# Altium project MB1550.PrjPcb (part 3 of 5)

## Sheet MCU_IO.SchDoc: MCU IOs
size A3; Date: Not used; ApprovedBy: Not used; CheckedBy: Not used; Author: Not used; CompanyName: STMicroelectronics; DrawnBy: Not used; Engineer: Not used; Organization: Not used; Address1: Not used; Address2: Not used; Address3: Not used; Address4: Not used; DocumentNumber: 3; Revision: Not used; SheetNumber: 3; SheetTotal: 24
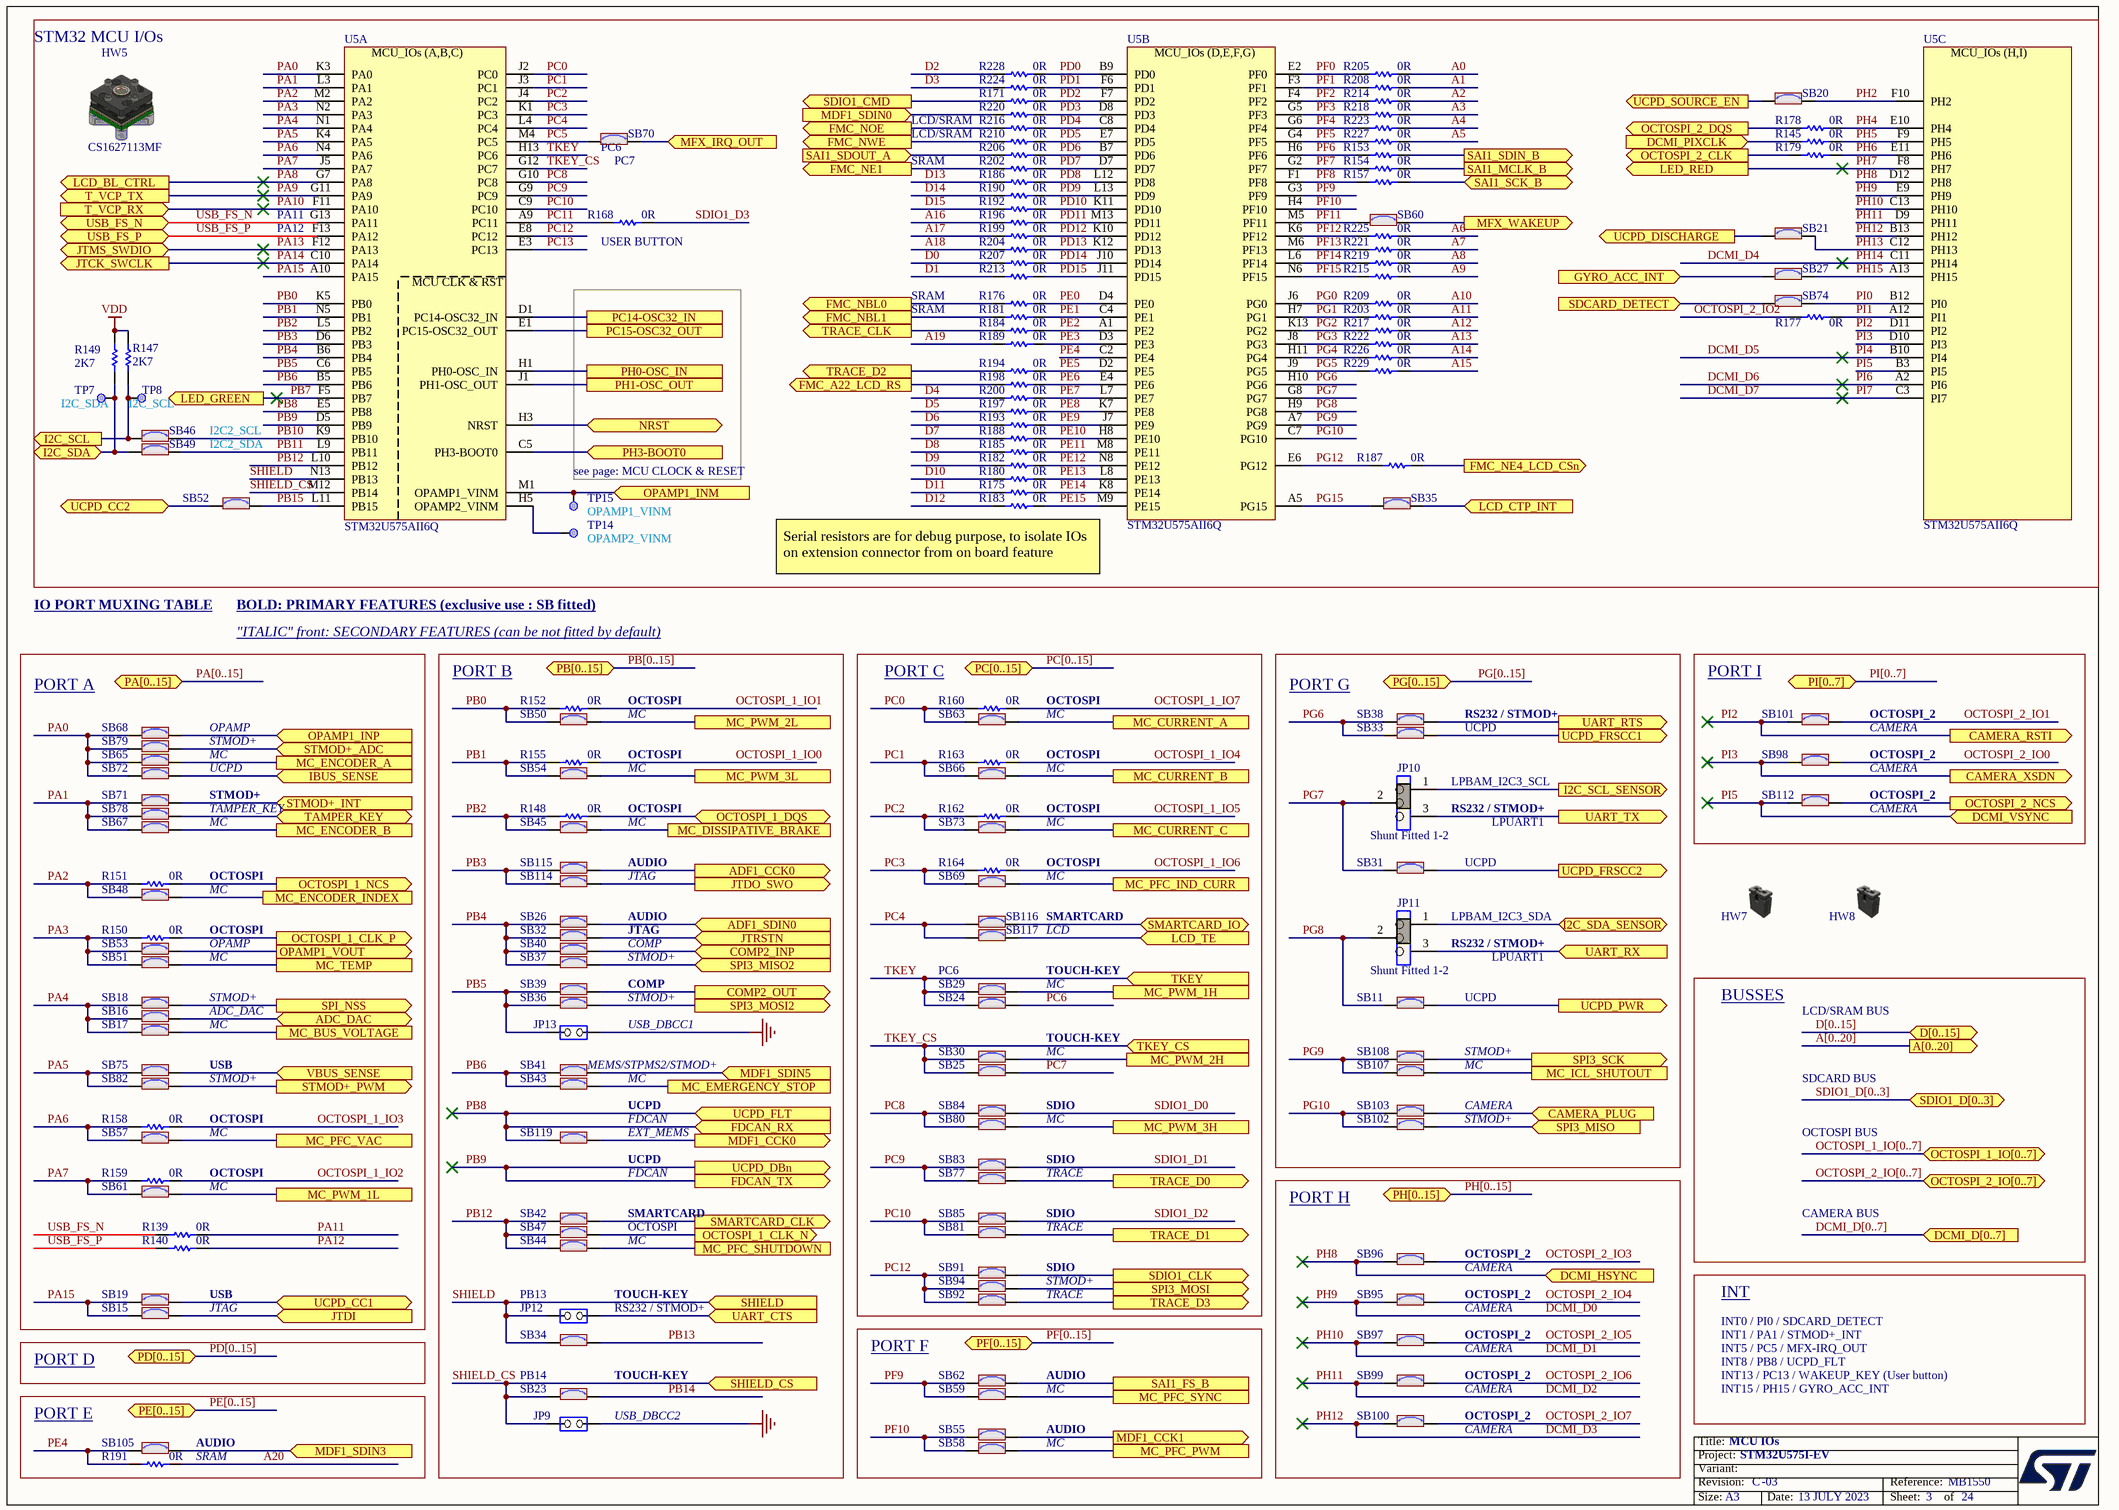
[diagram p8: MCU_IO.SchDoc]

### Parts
HW5  value CS1627113MF  (mechanical)
HW7  (no value)  (mechanical)
HW8  (no value)  (mechanical)
JP9  Jumper_Header 2x1  [CON_SAMTEC_TSW-102-07-G-S]  (value not drawn)
JP10  value Shunt Fitted 1-2  [CON_SAMTEC_TSW-103-07-F-S]
JP11  value Shunt Fitted 1-2  [CON_SAMTEC_TSW-103-07-F-S]
JP12  Jumper_Header 2x1  [CON_SAMTEC_TSW-102-07-G-S]  (value not drawn)
JP13  Jumper_Header 2x1  [CON_SAMTEC_TSW-102-07-G-S]  (value not drawn)
R139  value 0R  [R0402]  (hidden comment: Resistor)
R140  value 0R  [R0402]  (hidden comment: Resistor)
R145  value 0R  [R0402]  (hidden comment: Resistor)
R147  value 2K7  [R0603]  (hidden comment: Resistor)
R148  value 0R  [R0402]
R149  value 2K7  [R0603]  (hidden comment: Resistor)
R150  value 0R  [R0402]
R151  value 0R  [R0402]
R152  value 0R  [R0402]
R153  value 0R  [R0603]
R154  value 0R  [R0603]
R155  value 0R  [R0402]
R157  value 0R  [R0603]
R158  value 0R  [R0402]
R159  value 0R  [R0402]
R160  value 0R  [R0402]
R162  value 0R  [R0402]
R163  value 0R  [R0402]
R164  value 0R  [R0402]
R168  value 0R  [R0603]
R171  value 0R  [R0603]
R175  value 0R  [R0402]  (hidden comment: Resistor)
R176  value 0R  [R0603]
R177  value 0R  [R0402]  (hidden comment: Resistor)
R178  value 0R  [R0402]  (hidden comment: Resistor)
R179  value 0R  [R0402]  (hidden comment: Resistor)
R180  value 0R  [R0402]  (hidden comment: Resistor)
R181  value 0R  [R0603]
R182  value 0R  [R0402]  (hidden comment: Resistor)
R183  value 0R  [R0402]  (hidden comment: Resistor)
R184  value 0R  [R0603]
R185  value 0R  [R0402]  (hidden comment: Resistor)
R186  value 0R  [R0402]  (hidden comment: Resistor)
R187  value 0R  [R0603]
R188  value 0R  [R0402]  (hidden comment: Resistor)
R189  value 0R  [R0402]  (hidden comment: Resistor)
R190  value 0R  [R0402]  (hidden comment: Resistor)
R191  value 0R  [R0402]  (hidden comment: Resistor)
R192  value 0R  [R0402]  (hidden comment: Resistor)
R193  value 0R  [R0402]  (hidden comment: Resistor)
R194  value 0R  [R0603]
R196  value 0R  [R0402]  (hidden comment: Resistor)
R197  value 0R  [R0402]  (hidden comment: Resistor)
R198  value 0R  [R0402]  (hidden comment: Resistor)
R199  value 0R  [R0402]  (hidden comment: Resistor)
R200  value 0R  [R0402]  (hidden comment: Resistor)
R202  value 0R  [R0603]
R203  value 0R  [R0402]  (hidden comment: Resistor)
R204  value 0R  [R0402]  (hidden comment: Resistor)
R205  value 0R  [R0402]  (hidden comment: Resistor)
R206  value 0R  [R0603]
R207  value 0R  [R0402]  (hidden comment: Resistor)
R208  value 0R  [R0402]  (hidden comment: Resistor)
R209  value 0R  [R0402]  (hidden comment: Resistor)
R210  value 0R  [R0603]
R213  value 0R  [R0402]  (hidden comment: Resistor)
R214  value 0R  [R0402]  (hidden comment: Resistor)
R215  value 0R  [R0402]  (hidden comment: Resistor)
R216  value 0R  [R0603]
R217  value 0R  [R0402]  (hidden comment: Resistor)
R218  value 0R  [R0402]  (hidden comment: Resistor)
R219  value 0R  [R0402]  (hidden comment: Resistor)
R220  value 0R  [R0603]
R221  value 0R  [R0402]  (hidden comment: Resistor)
R222  value 0R  [R0402]  (hidden comment: Resistor)
R223  value 0R  [R0402]  (hidden comment: Resistor)
R224  value 0R  [R0402]  (hidden comment: Resistor)
R225  value 0R  [R0402]  (hidden comment: Resistor)
R226  value 0R  [R0402]  (hidden comment: Resistor)
R227  value 0R  [R0402]  (hidden comment: Resistor)
R228  value 0R  [R0402]  (hidden comment: Resistor)
R229  value 0R  [R0402]  (hidden comment: Resistor)
SB11  (no value)  [SOLDER-BRIDGE_R0603-0R]
SB15  (no value)  [SOLDER-BRIDGE_R0603-0R]
SB16  (no value)  [SOLDER-BRIDGE_R0603-0R]
SB17  (no value)  [SOLDER-BRIDGE_R0603-0R]
SB18  (no value)  [SOLDER-BRIDGE_R0603-0R]
SB19  (no value)  [SOLDER-BRIDGE_R0603-0R]
SB20  (no value)  [SOLDER-BRIDGE_R0603-0R]
SB21  (no value)  [SOLDER-BRIDGE_R0603-0R]
SB23  (no value)  [SOLDER-BRIDGE_R0603-0R]
SB24  (no value)  [SOLDER-BRIDGE_R0603-0R]
SB25  (no value)  [SOLDER-BRIDGE_R0603-0R]
SB26  (no value)  [SOLDER-BRIDGE_R0603-0R]
SB27  (no value)  [SOLDER-BRIDGE_R0603-0R]
SB29  (no value)  [SOLDER-BRIDGE_R0603-0R]
SB30  (no value)  [SOLDER-BRIDGE_R0603-0R]
SB31  (no value)  [SOLDER-BRIDGE_R0603-0R]
SB32  (no value)  [SOLDER-BRIDGE_R0603-0R]
SB33  (no value)  [SOLDER-BRIDGE_R0603-0R]
SB34  (no value)  [SOLDER-BRIDGE_R0603-0R]
SB35  (no value)  [SOLDER-BRIDGE_R0603-0R]
SB36  (no value)  [SOLDER-BRIDGE_R0603-0R]
SB37  (no value)  [SOLDER-BRIDGE_R0603-0R]
SB38  (no value)  [SOLDER-BRIDGE_R0603-0R]
SB39  (no value)  [SOLDER-BRIDGE_R0603-0R]
SB40  (no value)  [SOLDER-BRIDGE_R0603-0R]
SB41  (no value)  [SOLDER-BRIDGE_R0603-0R]
SB42  (no value)  [SOLDER-BRIDGE_R0603-0R]
SB43  (no value)  [SOLDER-BRIDGE_R0603-0R]
SB44  (no value)  [SOLDER-BRIDGE_R0603-0R]
SB45  (no value)  [SOLDER-BRIDGE_R0603-0R]
SB46  (no value)  [SOLDER-BRIDGE_R0603-0R]
SB47  (no value)  [SOLDER-BRIDGE_R0603-0R]
SB48  (no value)  [SOLDER-BRIDGE_R0603-0R]
SB49  (no value)  [SOLDER-BRIDGE_R0603-0R]
SB50  (no value)  [SOLDER-BRIDGE_R0603-0R]
SB51  (no value)  [SOLDER-BRIDGE_R0603-0R]
SB52  (no value)  [SOLDER-BRIDGE_R0603-0R]
SB53  (no value)  [SOLDER-BRIDGE_R0603-0R]
SB54  (no value)  [SOLDER-BRIDGE_R0603-0R]
SB55  (no value)  [SOLDER-BRIDGE_R0603-0R]
SB57  (no value)  [SOLDER-BRIDGE_R0603-0R]
SB58  (no value)  [SOLDER-BRIDGE_R0603-0R]
SB59  (no value)  [SOLDER-BRIDGE_R0603-0R]
SB60  (no value)  [SOLDER-BRIDGE_R0603-0R]
SB61  (no value)  [SOLDER-BRIDGE_R0603-0R]
SB62  (no value)  [SOLDER-BRIDGE_R0603-0R]
SB63  (no value)  [SOLDER-BRIDGE_R0603-0R]
SB65  (no value)  [SOLDER-BRIDGE_R0603-0R]
SB66  (no value)  [SOLDER-BRIDGE_R0603-0R]
SB67  (no value)  [SOLDER-BRIDGE_R0603-0R]
SB68  (no value)  [SOLDER-BRIDGE_R0603-0R]
SB69  (no value)  [SOLDER-BRIDGE_R0603-0R]
SB70  (no value)  [SOLDER-BRIDGE_R0603-0R]
SB71  (no value)  [SOLDER-BRIDGE_R0603-0R]
SB72  (no value)  [SOLDER-BRIDGE_R0603-0R]
SB73  (no value)  [SOLDER-BRIDGE_R0603-0R]
SB74  (no value)  [SOLDER-BRIDGE_R0603-0R]
SB75  (no value)  [SOLDER-BRIDGE_R0603-0R]
SB77  (no value)  [SOLDER-BRIDGE_R0603-0R]
SB78  (no value)  [SOLDER-BRIDGE_R0603-0R]
SB79  (no value)  [SOLDER-BRIDGE_R0603-0R]
SB80  (no value)  [SOLDER-BRIDGE_R0603-0R]
SB81  (no value)  [SOLDER-BRIDGE_R0603-0R]
SB82  (no value)  [SOLDER-BRIDGE_R0603-0R]
SB83  (no value)  [SOLDER-BRIDGE_R0603-0R]
SB84  (no value)  [SOLDER-BRIDGE_R0603-0R]
SB85  (no value)  [SOLDER-BRIDGE_R0603-0R]
SB91  (no value)  [SOLDER-BRIDGE_R0603-0R]
SB92  (no value)  [SOLDER-BRIDGE_R0603-0R]
SB94  (no value)  [SOLDER-BRIDGE_R0603-0R]
SB95  (no value)  [SOLDER-BRIDGE_R0603-0R]
SB96  (no value)  [SOLDER-BRIDGE_R0603-0R]
SB97  (no value)  [SOLDER-BRIDGE_R0603-0R]
SB98  (no value)  [SOLDER-BRIDGE_R0603-0R]
SB99  (no value)  [SOLDER-BRIDGE_R0603-0R]
SB100  (no value)  [SOLDER-BRIDGE_R0603-0R]
SB101  (no value)  [SOLDER-BRIDGE_R0603-0R]
SB102  (no value)  [SOLDER-BRIDGE_R0603-0R]
SB103  (no value)  [SOLDER-BRIDGE_R0603-0R]
SB105  (no value)  [SOLDER-BRIDGE_R0603-0R]
SB107  (no value)  [SOLDER-BRIDGE_R0603-0R]
SB108  (no value)  [SOLDER-BRIDGE_R0603-0R]
SB112  (no value)  [SOLDER-BRIDGE_R0603-0R]
SB114  (no value)  [SOLDER-BRIDGE_R0603-0R]
SB115  (no value)  [SOLDER-BRIDGE_R0603-0R]
SB116  (no value)  [SOLDER-BRIDGE_R0603-0R]
SB117  (no value)  [SOLDER-BRIDGE_R0603-0R]
SB119  (no value)  [SOLDER-BRIDGE_R0603-0R]
TP7  value I2C_SDA  [TP_SMD_1MM]  (no BOM)
TP8  value I2C_SCL  [TP_SMD_1MM]  (no BOM)
TP14  value OPAMP2_VINM  [TP_SMD_1MM]  (no BOM)
TP15  value OPAMP1_VINM  [TP_SMD_1MM]  (no BOM)
U5  value STM32U575AII6Q  [ICC_UFBGA169_7X7_P050_PAD025-PM030-SM035_SOCKET_IRONWOOD_CS1627113MF_NM]  (hidden comment: STM32U575AII6QU)  (parts A,B,C of 4)

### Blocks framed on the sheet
STM32 MCU I/Os: HW5 R145 R147 R149 R153 R154 R157 R168 R171 R175-R190 R192-R194 R196-R200 R202-R210 R213-R229 SB20 SB21 SB27 SB35 SB46 SB49 SB52 SB60 SB70 SB74 TP7 TP8 TP14 TP15 U5
PORT A: R139 R140 R150 R151 R158 R159 SB15-SB19 SB48 SB51 SB53 SB57 SB61 SB65 SB67 SB68 SB71 SB72 SB75 SB78 SB79 SB82
PORT B: JP9 JP12 JP13 R148 R152 R155 SB23 SB26 SB32 SB34 SB36 SB37 SB39-SB45 SB47 SB50 SB54 SB114 SB115 SB119
PORT C: R160 R162-R164 SB24 SB25 SB29 SB30 SB63 SB66 SB69 SB73 SB77 SB80 SB81 SB83-SB85 SB91 SB92 SB94 SB116 SB117
PORT G: JP10 JP11 SB11 SB31 SB33 SB38 SB102 SB103 SB107 SB108
PORT I: SB98 SB101 SB112
PORT H: SB95-SB97 SB99 SB100
PORT F: SB55 SB58 SB59 SB62
PORT E: R191 SB105

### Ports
A[0..20] (out), ADC_DAC (bidir), ADF1_CCK0 (out), ADF1_SDIN0 (in), CAMERA_PLUG (in), CAMERA_RSTI (out), CAMERA_XSDN (out), COMP2_INP (in), COMP2_OUT (out), D[0..15] (bidir), DCMI_D[0..7] (in), DCMI_HSYNC (in), DCMI_PIXCLK (in), DCMI_VSYNC (in), FDCAN_RX (in), FDCAN_TX (out), FMC_A22_LCD_RS (out), FMC_NBL0 (out), FMC_NBL1 (out), FMC_NE1 (out), FMC_NE4_LCD_CSn (out), FMC_NOE (out), FMC_NWE (out), GYRO_ACC_INT (in), I2C_SCL (out), I2C_SCL_SENSOR (out), I2C_SDA (bidir), I2C_SDA_SENSOR (bidir), IBUS_SENSE (in), JTCK_SWCLK (out), JTDI (in), JTDO_SWO (out), JTMS_SWDIO (bidir), JTRSTN (in), LCD_BL_CTRL (out), LCD_CTP_INT (in), LCD_TE (in), LED_GREEN (out), LED_RED (out), MC_BUS_VOLTAGE, MC_CURRENT_A, MC_CURRENT_B, MC_CURRENT_C, MC_DISSIPATIVE_BRAKE, MC_EMERGENCY_STOP, MC_ENCODER_A, MC_ENCODER_B, MC_ENCODER_INDEX, MC_ICL_SHUTOUT, MC_PFC_IND_CURR, MC_PFC_PWM, MC_PFC_SHUTDOWN, MC_PFC_SYNC, MC_PFC_VAC, MC_PWM_1H, MC_PWM_1L, MC_PWM_2H, MC_PWM_2L, MC_PWM_3H, MC_PWM_3L, MC_TEMP, MDF1_CCK0 (out), MDF1_CCK1 (out), MDF1_SDIN0 (in), MDF1_SDIN3 (in), MDF1_SDIN5 (in), MFX_IRQ_OUT (in), MFX_WAKEUP (out), NRST (bidir), OCTOSPI_1_CLK_N (out), OCTOSPI_1_CLK_P (out), OCTOSPI_1_DQS (bidir), OCTOSPI_1_IO[0..7] (bidir), OCTOSPI_1_NCS (out), OCTOSPI_2_CLK (out), OCTOSPI_2_DQS (out), OCTOSPI_2_IO[0..7] (bidir), OCTOSPI_2_NCS (out), OPAMP1_INM (in), OPAMP1_INP (in), OPAMP1_VOUT (out), PA[0..15] (bidir), PB[0..15] (bidir), PC14-OSC32_IN, PC15-OSC32_OUT, PC[0..15] (bidir), PD[0..15] (bidir), PE[0..15] (bidir), PF[0..15] (bidir), PG[0..15] (bidir), PH0-OSC_IN, PH1-OSC_OUT, PH3-BOOT0 (in), PH[0..15] (bidir), PI[0..7] (bidir), SAI1_FS_B, SAI1_MCLK_B (out), SAI1_SCK_B (bidir), SAI1_SDIN_B (out), SAI1_SDOUT_A (in), SDCARD_DETECT (in), SDIO1_CLK (out), SDIO1_CMD (out), SDIO1_D[0..3] (bidir), SHIELD (in), SHIELD_CS (in), SMARTCARD_CLK (out), SMARTCARD_IO (bidir), SPI3_MISO2 (in), SPI3_MISO (in), SPI3_MOSI2 (out), SPI3_MOSI (out), SPI3_SCK (out), SPI_NSS (out), STMOD+_ADC (in), STMOD+_INT (in), STMOD+_PWM (out), T_VCP_RX (in), T_VCP_TX (out), TAMPER_KEY (bidir), TKEY (in), TKEY_CS (in), TRACE_CLK (out), TRACE_D0 (out), TRACE_D1 (out), TRACE_D2 (out), TRACE_D3 (out), UART_CTS (in), UART_RTS (out), UART_RX (in), UART_TX (out), UCPD_CC1 (bidir), UCPD_CC2 (bidir), UCPD_DBn (out), UCPD_DISCHARGE (out), UCPD_FLT (in), UCPD_FRSCC1 (out), UCPD_FRSCC2 (out), UCPD_PWR (out), UCPD_SOURCE_EN (out), USB_FS_N (bidir), USB_FS_P (bidir), VBUS_SENSE (in)

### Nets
GND: JP9.2(NO) JP13.2(NO)
VDD: R147.2 R149.2
A0: R205.2
A1: R208.2
A2: R214.2
A3: R218.2
A4: R223.2
A5: R227.2
A6: R225.2
A7: R221.2
A8: R219.2
A9: R215.2
A10: R209.2
A11: R203.2
A12: R217.2
A13: R222.2
A14: R226.2
A15: R229.2
A16: R196.1
A17: R199.1
A18: R204.1
A19: R189.1
A20: R191.2
ADC_DAC: SB16.2 ; port ADC_DAC
ADF1_CCK0: SB115.2 ; port ADF1_CCK0
ADF1_SDIN0: SB26.2 ; port ADF1_SDIN0
CAMERA_PLUG: SB103.2 ; port CAMERA_PLUG
COMP2_INP: SB40.2 ; port COMP2_INP
COMP2_OUT: SB39.2 ; port COMP2_OUT
D0: R207.1
D1: R213.1
D2: R228.1
D3: R224.1
D4: R200.1
D5: R197.1
D6: R193.1
D7: R188.1
D8: R185.1
D9: R182.1
D10: R180.1
D11: R175.1
D12: R183.1
D13: R186.1
D14: R190.1
D15: R192.1
DCMI_D0: SB95.1 U5.E9(PH9)  [also labelled PH9]
DCMI_D1: SB97.1 U5.C13(PH10)  [also labelled PH10]
DCMI_D2: SB99.1 U5.D9(PH11)  [also labelled PH11]
DCMI_D3: SB100.1 U5.B13(PH12)  [also labelled PH12]
DCMI_D4: U5.C11(PH14)  [also labelled PH14]
DCMI_D5: U5.B10(PI4)  [also labelled PI4]
DCMI_D6: U5.A2(PI6)  [also labelled PI6]
DCMI_D7: U5.C3(PI7)  [also labelled PI7]
DCMI_PIXCLK: R145.1 ; port DCMI_PIXCLK
FMC_A22_LCD_RS: R198.1 ; port FMC_A22_LCD_RS
FMC_NBL0: R176.1 ; port FMC_NBL0
FMC_NBL1: R181.1 ; port FMC_NBL1
FMC_NE1: R202.1 ; port FMC_NE1
FMC_NE4_LCD_CSn: R187.2 ; port FMC_NE4_LCD_CSn
FMC_NOE: R216.1 ; port FMC_NOE
FMC_NWE: R210.1 ; port FMC_NWE
GYRO_ACC_INT: SB27.1 ; port GYRO_ACC_INT
I2C_SCL: R147.1 SB46.1 TP8.1 ; port I2C_SCL
I2C_SCL_SENSOR: JP10.1 ; port I2C_SCL_SENSOR
I2C_SDA: R149.1 SB49.1 TP7.1 ; port I2C_SDA
I2C_SDA_SENSOR: JP11.1 ; port I2C_SDA_SENSOR
IBUS_SENSE: SB72.2 ; port IBUS_SENSE
JTDI: SB15.2 ; port JTDI
JTDO_SWO: SB114.2 ; port JTDO_SWO
JTRSTN: SB32.2 ; port JTRSTN
LCD_CTP_INT: SB35.2 ; port LCD_CTP_INT
LCD_TE: SB117.2 ; port LCD_TE
MC_BUS_VOLTAGE: SB17.2 ; port MC_BUS_VOLTAGE
MC_CURRENT_A: SB63.2 ; port MC_CURRENT_A
MC_CURRENT_B: SB66.2 ; port MC_CURRENT_B
MC_CURRENT_C: SB73.2 ; port MC_CURRENT_C
MC_DISSIPATIVE_BRAKE: SB45.2 ; port MC_DISSIPATIVE_BRAKE
MC_EMERGENCY_STOP: SB43.2 ; port MC_EMERGENCY_STOP
MC_ENCODER_A: SB65.2 ; port MC_ENCODER_A
MC_ENCODER_B: SB67.2 ; port MC_ENCODER_B
MC_ENCODER_INDEX: SB48.2 ; port MC_ENCODER_INDEX
MC_ICL_SHUTOUT: SB107.2 ; port MC_ICL_SHUTOUT
MC_PFC_IND_CURR: SB69.2 ; port MC_PFC_IND_CURR
MC_PFC_PWM: SB58.2 ; port MC_PFC_PWM
MC_PFC_SHUTDOWN: SB44.2 ; port MC_PFC_SHUTDOWN
MC_PFC_SYNC: SB59.2 ; port MC_PFC_SYNC
MC_PFC_VAC: SB57.2 ; port MC_PFC_VAC
MC_PWM_1H: SB29.2 ; port MC_PWM_1H
MC_PWM_1L: SB61.2 ; port MC_PWM_1L
MC_PWM_2H: SB30.2 ; port MC_PWM_2H
MC_PWM_2L: SB50.2 ; port MC_PWM_2L
MC_PWM_3H: SB80.2 ; port MC_PWM_3H
MC_PWM_3L: SB54.2 ; port MC_PWM_3L
MC_TEMP: SB51.2 ; port MC_TEMP
MDF1_CCK0: SB119.2 ; port MDF1_CCK0
MDF1_CCK1: SB55.2 ; port MDF1_CCK1
MDF1_SDIN0: R220.1 ; port MDF1_SDIN0
MDF1_SDIN3: SB105.2 ; port MDF1_SDIN3
MDF1_SDIN5: SB41.2 ; port MDF1_SDIN5
MFX_IRQ_OUT: SB70.2 ; port MFX_IRQ_OUT
MFX_WAKEUP: SB60.2 ; port MFX_WAKEUP
NRST: U5.H3(NRST) ; port NRST
OCTOSPI_1_CLK_N: SB47.2 ; port OCTOSPI_1_CLK_N
OCTOSPI_1_CLK_P: R150.2 ; port OCTOSPI_1_CLK_P
OCTOSPI_1_DQS: R148.2 ; port OCTOSPI_1_DQS
OCTOSPI_1_IO0: R155.2
OCTOSPI_1_IO1: R152.2
OCTOSPI_1_IO2: R159.2
OCTOSPI_1_IO3: R158.2
OCTOSPI_1_IO4: R163.2
OCTOSPI_1_IO5: R162.2
OCTOSPI_1_IO6: R164.2
OCTOSPI_1_IO7: R160.2
OCTOSPI_1_NCS: R151.2 ; port OCTOSPI_1_NCS
OCTOSPI_2_CLK: R179.1 ; port OCTOSPI_2_CLK
OCTOSPI_2_DQS: R178.1 ; port OCTOSPI_2_DQS
OCTOSPI_2_IO0: SB98.2
OCTOSPI_2_IO1: SB101.2
OCTOSPI_2_IO2: R177.1
OCTOSPI_2_IO3: SB96.2
OCTOSPI_2_IO4: SB95.2
OCTOSPI_2_IO5: SB97.2
OCTOSPI_2_IO6: SB99.2
OCTOSPI_2_IO7: SB100.2
OCTOSPI_2_NCS: SB112.2 ; port OCTOSPI_2_NCS
OPAMP1_INM: TP15.1 U5.M1(OPAMP1_VINM) ; port OPAMP1_INM
OPAMP1_INP: SB68.2 ; port OPAMP1_INP
OPAMP1_VOUT: SB53.2 ; port OPAMP1_VOUT
PA0: SB65.1 SB68.1 SB72.1 SB79.1 U5.K3(PA0)
PA1: SB67.1 SB71.1 SB78.1 U5.L3(PA1)
PA2: R151.1 SB48.1 U5.M2(PA2)
PA3: R150.1 SB51.1 SB53.1 U5.N2(PA3)
PA4: SB16.1 SB17.1 SB18.1 U5.N1(PA4)
PA5: SB75.1 SB82.1 U5.K4(PA5)
PA6: R158.1 SB57.1 U5.N4(PA6)
PA7: R159.1 SB61.1 U5.J5(PA7)
PA8: U5.G7(PA8) ; port LCD_BL_CTRL
PA9: U5.G11(PA9) ; port T_VCP_TX
PA10: U5.F11(PA10) ; port T_VCP_RX
PA11: R139.2
PA12: R140.2
PA13: U5.F12(PA13) ; port JTMS_SWDIO  [project net JTMS_SWDIO]
PA14: U5.C10(PA14) ; port JTCK_SWCLK  [project net JTCK_SWCLK]
PA15: SB15.1 SB19.1 U5.A10(PA15)
PB0: R152.1 SB50.1 U5.K5(PB0)
PB1: R155.1 SB54.1 U5.N5(PB1)
PB2: R148.1 SB45.1 U5.L5(PB2)
PB3: SB114.1 SB115.1 U5.D6(PB3)
PB4: SB26.1 SB32.1 SB37.1 SB40.1 U5.B6(PB4)
PB5: JP13.1(COMMON) SB36.1 SB39.1 U5.C6(PB5)
PB6: SB41.1 SB43.1 U5.B5(PB6)
PB7: U5.F5(PB7) ; port LED_GREEN
PB8: SB119.1 U5.E5(PB8) ; port UCPD_FLT, port FDCAN_RX
PB9: U5.D5(PB9) ; port UCPD_DBn, port FDCAN_TX
PB10: SB46.2 U5.K9(PB10)
PB11: SB49.2 U5.L9(PB11)
PB12: SB42.1 SB44.1 SB47.1 U5.L10(PB12)
PB13: SB34.2
PB14: SB23.2
PB15: SB52.2 U5.L11(PB15)
PC0: R160.1 SB63.1 U5.J2(PC0)
PC1: R163.1 SB66.1 U5.J3(PC1)
PC2: R162.1 SB73.1 U5.J4(PC2)
PC3: R164.1 SB69.1 U5.K1(PC3)
PC4: SB116.1 SB117.1 U5.L4(PC4)
PC5: SB70.1 U5.M4(PC5)
PC6: SB24.2
PC7: SB25.2
PC8: SB80.1 SB84.1 U5.G10(PC8)
PC9: SB77.1 SB83.1 U5.G9(PC9)
PC10: SB81.1 SB85.1 U5.C9(PC10)
PC11: R168.1 U5.A9(PC11)
PC12: SB91.1 SB92.1 SB94.1 U5.E8(PC12)
PC13: U5.E3(PC13)
PC14-OSC32_IN: U5.D1(PC14-OSC32_IN) ; port PC14-OSC32_IN
PC15-OSC32_OUT: U5.E1(PC15-OSC32_OUT) ; port PC15-OSC32_OUT
PD0: R228.2 U5.B9(PD0)
PD1: R224.2 U5.F6(PD1)
PD2: R171.2 U5.F7(PD2)
PD3: R220.2 U5.D8(PD3)
PD4: R216.2 U5.C8(PD4)
PD5: R210.2 U5.E7(PD5)
PD6: R206.2 U5.B7(PD6)
PD7: R202.2 U5.D7(PD7)
PD8: R186.2 U5.L12(PD8)
PD9: R190.2 U5.L13(PD9)
PD10: R192.2 U5.K11(PD10)
PD11: R196.2 U5.M13(PD11)
PD12: R199.2 U5.K10(PD12)
PD13: R204.2 U5.K12(PD13)
PD14: R207.2 U5.J10(PD14)
PD15: R213.2 U5.J11(PD15)
PE0: R176.2 U5.D4(PE0)
PE1: R181.2 U5.C4(PE1)
PE2: R184.2 U5.A1(PE2)
PE3: R189.2 U5.D3(PE3)
PE4: R191.1 SB105.1 U5.C2(PE4)
PE5: R194.2 U5.D2(PE5)
PE6: R198.2 U5.E4(PE6)
PE7: R200.2 U5.L7(PE7)
PE8: R197.2 U5.K7(PE8)
PE9: R193.2 U5.J7(PE9)
PE10: R188.2 U5.H8(PE10)
PE11: R185.2 U5.M8(PE11)
PE12: R182.2 U5.N8(PE12)
PE13: R180.2 U5.L8(PE13)
PE14: R175.2 U5.K8(PE14)
PE15: R183.2 U5.M9(PE15)
PF0: R205.1 U5.E2(PF0)
PF1: R208.1 U5.F3(PF1)
PF2: R214.1 U5.F4(PF2)
PF3: R218.1 U5.G5(PF3)
PF4: R223.1 U5.G6(PF4)
PF5: R227.1 U5.G4(PF5)
PF6: R153.1 U5.H6(PF6)
PF7: R154.1 U5.G2(PF7)
PF8: R157.1 U5.F1(PF8)
PF9: SB59.1 SB62.1 U5.G3(PF9)
PF10: SB55.1 SB58.1 U5.H4(PF10)
PF11: SB60.1 U5.M5(PF11)
PF12: R225.1 U5.K6(PF12)
PF13: R221.1 U5.M6(PF13)
PF14: R219.1 U5.L6(PF14)
PF15: R215.1 U5.N6(PF15)
PG0: R209.1 U5.J6(PG0)
PG1: R203.1 U5.H7(PG1)
PG2: R217.1 U5.K13(PG2)
PG3: R222.1 U5.J8(PG3)
PG4: R226.1 U5.H11(PG4)
PG5: R229.1 U5.J9(PG5)
PG6: SB33.1 SB38.1 U5.H10(PG6)
PG7: JP10.2 SB31.1 U5.G8(PG7)
PG8: JP11.2 SB11.1 U5.H9(PG8)
PG9: SB107.1 SB108.1 U5.A7(PG9)
PG10: SB102.1 SB103.1 U5.C7(PG10)
PG12: R187.1 U5.E6(PG12)
PG15: SB35.1 U5.A5(PG15)
PH0-OSC_IN: U5.H1(PH0-OSC_IN) ; port PH0-OSC_IN
PH1-OSC_OUT: U5.J1(PH1-OSC_OUT) ; port PH1-OSC_OUT
PH2: SB20.2 U5.F10(PH2)
PH3-BOOT0: U5.C5(PH3-BOOT0) ; port PH3-BOOT0
PH4: R178.2 U5.E10(PH4)
PH5: R145.2 U5.F9(PH5)
PH6: R179.2 U5.E11(PH6)
PH7: U5.F8(PH7) ; port LED_RED
PH8: SB96.1 U5.D12(PH8) ; port DCMI_HSYNC
PH13: SB21.2 U5.C12(PH13)
PH15: SB27.2 U5.A13(PH15)
PI0: SB74.2 U5.B12(PI0)
PI1: R177.2 U5.A12(PI1)
PI2: SB101.1 U5.D11(PI2) ; port CAMERA_RSTI
PI3: SB98.1 U5.D10(PI3) ; port CAMERA_XSDN
PI5: SB112.1 U5.B3(PI5) ; port DCMI_VSYNC
SAI1_FS_B: SB62.2 ; port SAI1_FS_B
SAI1_MCLK_B: R154.2 ; port SAI1_MCLK_B
SAI1_SCK_B: R157.2 ; port SAI1_SCK_B
SAI1_SDIN_B: R153.2 ; port SAI1_SDIN_B
SAI1_SDOUT_A: R206.1 ; port SAI1_SDOUT_A
SDCARD_DETECT: SB74.1 ; port SDCARD_DETECT
SDIO1_CLK: SB91.2 ; port SDIO1_CLK
SDIO1_CMD: R171.1 ; port SDIO1_CMD
SDIO1_D0: SB84.2
SDIO1_D1: SB83.2
SDIO1_D2: SB85.2
SDIO1_D3: R168.2
SHIELD: JP12.1(COMMON) SB34.1 U5.N13(PB13) ; port SHIELD
SHIELD_CS: JP9.1(COMMON) SB23.1 U5.M12(PB14) ; port SHIELD_CS
SMARTCARD_CLK: SB42.2 ; port SMARTCARD_CLK
SMARTCARD_IO: SB116.2 ; port SMARTCARD_IO
SPI3_MISO: SB102.2 ; port SPI3_MISO
SPI3_MISO2: SB37.2 ; port SPI3_MISO2
SPI3_MOSI: SB94.2 ; port SPI3_MOSI
SPI3_MOSI2: SB36.2 ; port SPI3_MOSI2
SPI3_SCK: SB108.2 ; port SPI3_SCK
SPI_NSS: SB18.2 ; port SPI_NSS
STMOD+_ADC: SB79.2 ; port STMOD+_ADC
STMOD+_INT: SB71.2 ; port STMOD+_INT
STMOD+_PWM: SB82.2 ; port STMOD+_PWM
TAMPER_KEY: SB78.2 ; port TAMPER_KEY
TKEY: SB24.1 SB29.1 U5.H13(PC6) ; port TKEY
TKEY_CS: SB25.1 SB30.1 U5.G12(PC7) ; port TKEY_CS
TRACE_CLK: R184.1 ; port TRACE_CLK
TRACE_D0: SB77.2 ; port TRACE_D0
TRACE_D1: SB81.2 ; port TRACE_D1
TRACE_D2: R194.1 ; port TRACE_D2
TRACE_D3: SB92.2 ; port TRACE_D3
UART_CTS: JP12.2(NO) ; port UART_CTS
UART_RTS: SB38.2 ; port UART_RTS
UART_RX: JP11.3 ; port UART_RX
UART_TX: JP10.3 ; port UART_TX
UCPD_CC1: SB19.2 ; port UCPD_CC1
UCPD_CC2: SB52.1 ; port UCPD_CC2
UCPD_DISCHARGE: SB21.1 ; port UCPD_DISCHARGE
UCPD_FRSCC1: SB33.2 ; port UCPD_FRSCC1
UCPD_FRSCC2: SB31.2 ; port UCPD_FRSCC2
UCPD_PWR: SB11.2 ; port UCPD_PWR
UCPD_SOURCE_EN: SB20.1 ; port UCPD_SOURCE_EN
USB_FS_N: R139.1 U5.G13(PA11) ; port USB_FS_N
USB_FS_P: R140.1 U5.F13(PA12) ; port USB_FS_P
VBUS_SENSE: SB75.2 ; port VBUS_SENSE
NetTP14_1: TP14.1 U5.H5(OPAMP2_VINM)

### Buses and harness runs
bus A[0..20] = port A[0..20]
bus D[0..15] = port D[0..15]
bus DCMI_D[0..7] = port DCMI_D[0..7]
bus OCTOSPI_1_IO[0..7] = port OCTOSPI_1_IO[0..7]
bus OCTOSPI_2_IO[0..7] = port OCTOSPI_2_IO[0..7]
bus PA[0..15] = port PA[0..15]
bus PB[0..15] = port PB[0..15]
bus PC[0..15] = port PC[0..15]
bus PD[0..15] = port PD[0..15]
bus PE[0..15] = port PE[0..15]
bus PF[0..15] = port PF[0..15]
bus PG[0..15] = port PG[0..15]
bus PH[0..15] = port PH[0..15]
bus PI[0..7] = port PI[0..7]
bus SDIO1_D[0..3] = port SDIO1_D[0..3]

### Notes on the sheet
- (near SB70) PC6
- (near SB70) PC7
- LCD/SRAM
- SRAM
- (near U5) PA11
- (near U5) PA12
- (near R168) USER BUTTON
- I2C2_SCL
- I2C2_SDA
- (near TP15) see page: MCU CLOCK & RESET
- (near R183) Serial resistors are for debug purpose, to isolate IOs on extension connector from on board feature
- IO PORT MUXING TABLE
- BOLD: PRIMARY FEATURES (exclusive use : SB fitted)
- "ITALIC" front: SECONDARY FEATURES (can be not fitted by default)
- MC
- OCTOSPI
- RS232 / STMOD+
- OCTOSPI_2
- OPAMP
- STMOD+
- UCPD
- LPBAM_I2C3_SCL
- CAMERA
- TAMPER_KEY
- LPUART1
- JTAG
- AUDIO
- SMARTCARD
- LPBAM_I2C3_SDA
- (near SB31) UCPD
- COMP
- PC6
- TOUCH-KEY
- LCD
- ADC_DAC
- USB_DBCC1
- (near SB11) UCPD
- BUSSES
- LCD/SRAM BUS
- USB
- (near SB41) MEMS/STPMS2/STMOD+
- FDCAN
- SDIO
- SDCARD BUS
- EXT_MEMS
- TRACE
- OCTOSPI BUS
- CAMERA BUS
- PB13
- INT
- INT0 / PI0 / SDCARD_DETECT
- PORT D
- PB14
- INT1 / PA1 / STMOD+_INT
- INT5 / PC5 / MFX-IRQ_OUT
- INT8 / PB8 / UCPD_FLT
- INT13 / PC13 / WAKEUP_KEY (User button)
- INT15 / PH15 / GYRO_ACC_INT
- USB_DBCC2

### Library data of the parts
HW5 = MCD-01903: IRONWOOD SOCKET for BGA169 16.73x16.73x14.09 pitch 0.5mm array 13x13; Part_Type: Misc; Provided_By: SUBCO with ST control
HW7 HW8 = MCD-00043: SHUNT 2.54mm BLACK; Manufacturer_Part_Number: SNT-100-BK-G; Manufacturer: SAMTEC; Part_Type: Mechanical; Provided_By: Subcon; Initial_Board_Reference: MB1274
JP9 JP12 JP13 = MCD-00045: Header, 2x1, 2,54mm, VR, TH, Height 5.84mm/2.54mm; Part_Type: Connector; Manufacturer_Part_Number: TSW-102-07-x-S; Manufacturer: SAMTEC; Value: Shunt not fitted; Provided_By: Subcon; Initial_Board_Reference: MB1274; Remark: 3D KO: BZ: 40098
JP10 JP11 = MCD-00684: Header, 3x1, 2,54mm, VR, TH, Height 5.84mm/2.54mm - Shunt Fitted 1-2 by default; Part_Type: Connector; Manufacturer_Part_Number: TSW-103-07-F-S; Manufacturer: SAMTEC; Provided_By: Subcon; Initial_Board_Reference: MB1331
R139 R140 R145 R175 R177-R180 R182 R183 R185 R186 R188-R193 R196-R200 R203-R205 R207-R209 R213-R215 R217-R219 R221-R229 = MCD-00052: Resistor,0R,0402,5%,1/16W; Manufacturer_Part_Number: RC0402JR-070RL; Manufacturer: YAGEO; ECCN_US: EAR99; ECCN_EU: NEC; Provided_By: SUBCO
R147 R149 = MCD-00218: Resistor,2K7,0603,1%,1/10W; Manufacturer_Part_Number: RC0603FR-072K7L; Manufacturer: YAGEO; BMS_Part_Number: 9129767; ECCN_US: EAR99; ECCN_EU: NEC; Provided_By: SUBCO
R148 R150-R152 R155 R158-R160 R162-R164 = MCD-00052: Resistor,0R,0402,5%,1/16W; Manufacturer_Part_Number: RC0402JR-070RL; Manufacturer: YAGEO; Provided_By: Subcon; Initial_Board_Reference: MB1274
R153 R154 R157 R168 R171 R176 R181 R184 R187 R194 R202 R206 R210 R216 R220 = MCD-00056: Resistor,0R,0603,5%,1/10W; Manufacturer_Part_Number: RC0603JR-070RL; Manufacturer: YAGEO; Provided_By: subcon; Initial_Board_Reference: MB1274
SB11 SB15-SB21 SB23-SB27 SB29-SB55 SB57-SB63 SB65-SB75 SB77-SB85 SB91 SB92 SB94-SB103 SB105 SB107 SB108 SB112 SB114-SB117 SB119 = MCD-00071: Solder Bridge ON; Part_Type: Mechanical; Provided_By: Subcon; Initial_Board_Reference: MB1274
TP7 TP8 TP14 TP15 = MCD-00074: Test Point 1mm; Part_Type: Mechanical; Initial_Board_Reference: MB1274
U5 = MCD-01902: MCU, STM32U575AII6Q,Low Power BGA169 7x7, pitch0.5, no AES, Q for Int SMPS, with socket footprint IRONWOOD CS1627113MF MCD-01903; Part_Type: IC; Manufacturer_Part_Number: STM32U575AII6Q (CS1627113MF); Manufacturer: STMICROELECTRONICS; Part_Preference: Recommended; Manufacturer_HQ_COO: EU; Component_Country_Of_Origin: Taiwan

## Sheet MCU_PWR.SchDoc: MCU PWR
size A4; Date: Not used; ApprovedBy: Not used; CheckedBy: Not used; Author: Not used; CompanyName: STMicroelectronics; DrawnBy: Not used; Engineer: Not used; Organization: Not used; Address1: Not used; Address2: Not used; Address3: Not used; Address4: Not used; DocumentNumber: 5; Revision: Not used; SheetNumber: 5; SheetTotal: 24
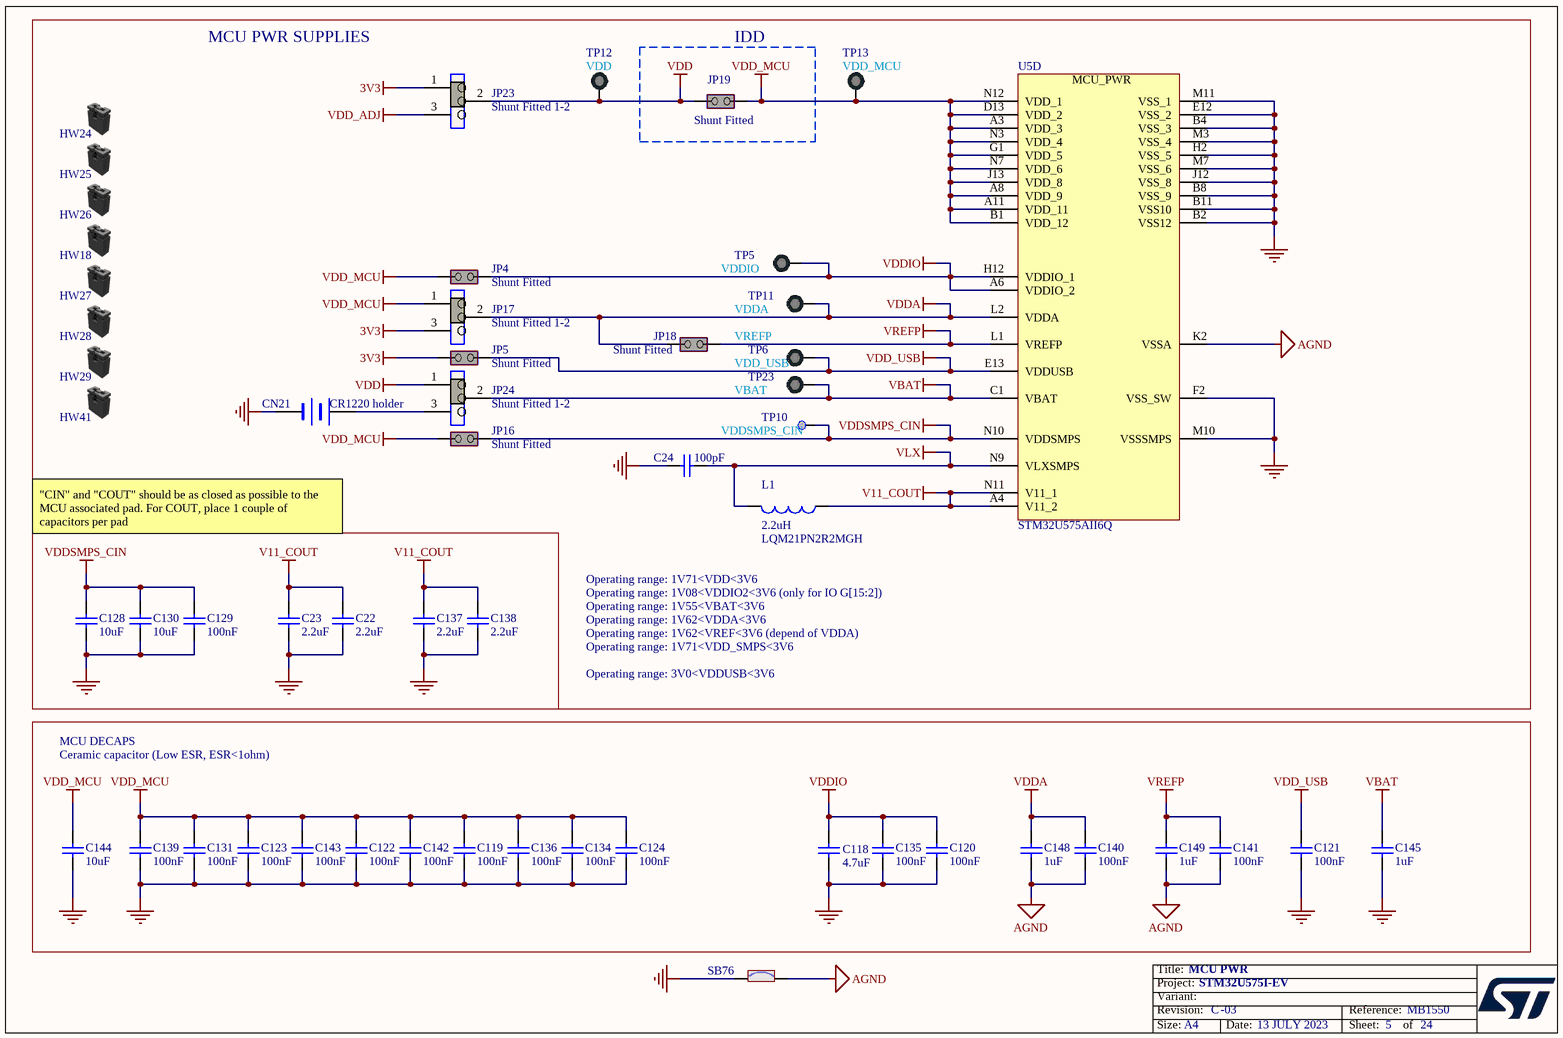
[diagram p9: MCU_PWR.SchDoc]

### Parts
C22  value 2.2uF  [C0402]
C23  value 2.2uF  [C0402]
C24  value 100pF  [C0402]
C118  value 4.7uF  [C0603]
C119  value 100nF  [C0402]
C120  value 100nF  [C0402]
C121  value 100nF  [C0402]
C122  value 100nF  [C0402]
C123  value 100nF  [C0402]
C124  value 100nF  [C0402]
C128  value 10uF  [C0402]  (hidden comment: Capacitor)
C129  value 100nF  [C0402]
C130  value 10uF  [C0402]  (hidden comment: Capacitor)
C131  value 100nF  [C0402]
C134  value 100nF  [C0402]
C135  value 100nF  [C0402]
C136  value 100nF  [C0402]
C137  value 2.2uF  [C0402]
C138  value 2.2uF  [C0402]
C139  value 100nF  [C0402]
C140  value 100nF  [C0402]
C141  value 100nF  [C0402]
C142  value 100nF  [C0402]
C143  value 100nF  [C0402]
C144  value 10uF  [C0402]  (hidden comment: Capacitor)
C145  value 1uF  [C0603]
C148  value 1uF  [C0603]
C149  value 1uF  [C0603]
CN21  value CR1220 holder  [BAT_HARWIN_S8411-45R_SMD_2P]
HW18  (no value)  (mechanical)
HW24  (no value)  (mechanical)
HW25  (no value)  (mechanical)
HW26  (no value)  (mechanical)
HW27  (no value)  (mechanical)
HW28  (no value)  (mechanical)
HW29  (no value)  (mechanical)
HW41  (no value)  (mechanical)
JP4  value Shunt Fitted  [CON_SAMTEC_TSW-102-07-G-S]
JP5  value Shunt Fitted  [CON_SAMTEC_TSW-102-07-G-S]
JP16  value Shunt Fitted  [CON_SAMTEC_TSW-102-07-G-S]
JP17  value Shunt Fitted 1-2  [CON_SAMTEC_TSW-103-07-F-S]
JP18  value Shunt Fitted  [CON_SAMTEC_TSW-102-07-G-S]
JP19  value Shunt Fitted  [CON_SAMTEC_TSW-102-07-G-S]
JP23  value Shunt Fitted 1-2  [CON_SAMTEC_TSW-103-07-F-S]
JP24  value Shunt Fitted 1-2  [CON_SAMTEC_TSW-103-07-F-S]
L1  value 2.2uH  Manufacturer_Part_Number: LQM21PN2R2MGH  [L0805_H0P9]  (hidden comment: Inductor)
SB76  (no value)  [SOLDER-BRIDGE_R0603-0R]
TP5  value VDDIO  [TP_PTH_1MM_2MM]  (no BOM)
TP6  value VDD_USB  [TP_PTH_1MM_2MM]  (no BOM)
TP10  value VDDSMPS_CIN  [TP_SMD_1MM]  (hidden comment: Test Point)  (no BOM)
TP11  value VDDA  [TP_PTH_1MM_2MM]  (no BOM)
TP12  value VDD  [TP_PTH_1MM_2MM]  (no BOM)
TP13  value VDD_MCU  [TP_PTH_1MM_2MM]  (no BOM)
TP23  value VBAT  [TP_PTH_1MM_2MM]  (no BOM)
U5  value STM32U575AII6Q  [ICC_UFBGA169_7X7_P050_PAD025-PM030-SM035_SOCKET_IRONWOOD_CS1627113MF_NM]  (hidden comment: STM32U575AII6QU)  (part D of 4)

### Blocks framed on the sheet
MCU PWR SUPPLIES: C22-C24 C128-C130 C137 C138 CN21 HW18 HW24-HW29 HW41 JP4 JP5 JP16-JP18 JP23 JP24 L1 TP5 TP6 TP10-TP13 TP23 U5
IDD: JP19

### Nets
3V3: JP5.1(COMMON) JP17.3 JP23.1
AGND: C140.1 C141.1 C148.2 C149.2 SB76.2 U5.K2(VSSA)
GND: C22.1 C23.1 C24.1 C118.1 C119.1 C120.1 C121.1 C122.1 C123.1 C124.1 C128.1 C129.1 C130.1 C131.1 C134.1 C135.1 C136.1 C137.1 C138.1 C139.1 C142.1 C143.1 C144.1 C145.2 CN21.2(-) SB76.1 U5.B2(VSS12) U5.B4(VSS_3) U5.B8(VSS_9) U5.B11(VSS10) U5.E12(VSS_2) U5.F2(VSS_SW) U5.H2(VSS_5) U5.J12(VSS_8) U5.M3(VSS_4) U5.M7(VSS_6) U5.M10(VSSSMPS) U5.M11(VSS_1)
V11_COUT: C22.2 C23.2 C137.2 C138.2 L1.1 U5.A4(V11_2) U5.N11(V11_1)
VBAT: C145.1 JP24.2 TP23.1 U5.C1(VBAT)
VDD: JP19.1(COMMON) JP23.2 JP24.1 TP12.1
VDD_ADJ: JP23.3
VDD_MCU: C119.2 C122.2 C123.2 C124.2 C131.2 C134.2 C136.2 C139.2 C142.2 C143.2 C144.2 JP4.1(COMMON) JP16.1(COMMON) JP17.1 JP19.2(NO) TP13.1 U5.A3(VDD_3) U5.A8(VDD_9) U5.A11(VDD_11) U5.B1(VDD_12) U5.D13(VDD_2) U5.G1(VDD_5) U5.J13(VDD_8) U5.N3(VDD_4) U5.N7(VDD_6) U5.N12(VDD_1)
VDD_USB: C121.2 JP5.2(NO) TP6.1 U5.E13(VDDUSB)
VDDA: C140.2 C148.1 JP17.2 JP18.1(COMMON) TP11.1 U5.L2(VDDA)
VDDIO: C118.2 C120.2 C135.2 JP4.2(NO) TP5.1 U5.A6(VDDIO_2) U5.H12(VDDIO_1)
VDDSMPS_CIN: C128.2 C129.2 C130.2 JP16.2(NO) TP10.1 U5.N10(VDDSMPS)
VLX: C24.2 L1.2 U5.N9(VLXSMPS)
VREFP: C141.2 C149.1 JP18.2(NO) U5.L1(VREFP)
NetCN21_1: CN21.1(+) JP24.3

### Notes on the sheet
- VREFP
- "CIN" and "COUT" should be as closed as possible to the MCU associated pad. For COUT, place 1 couple of capacitors per pad
- Operating range: 1V71<VDD<3V6
- Operating range: 1V08<VDDIO2<3V6 (only for IO G[15:2])
- Operating range: 1V62<VDDA<3V6
- Operating range: 1V55<VBAT<3V6
- Operating range: 1V71<VDD_SMPS<3V6
- Operating range: 1V62<VREF<3V6 (depend of VDDA)
- Operating range: 3V0<VDDUSB<3V6
- MCU DECAPS
- Ceramic capacitor (Low ESR, ESR<1ohm)

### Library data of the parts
C22 C23 C137 C138 = MCD-01823: Capacitor,MLCC,2.2uF,6V3,X5R,10%,0402,T=0.5; Manufacturer_Part_Number: GRM155R60J225KE95D; Manufacturer: MURATA; ECCN_US: EAR99; ECCN_EU: NEC; Provided_By: SUBCO
C24 = MCD-00205: Capacitor, MLCC, 100pF, 50V, NPO, 5%, 0402, T=0,5mm; Manufacturer_Part_Number: CC0402JRNPO9BN101; Manufacturer: YAGEO; Provided_By: Subcon; Initial_Board_Reference: MB1361
C118 = MCD-00009: Capacitor, MLCC, 4.7uF, 16V, X5R, 10%, 0603, T=0.8mm; Manufacturer_Part_Number: CC0603KRX5R7BB475; Manufacturer: YAGEO; ECCN_US: EAR99; ECCN_EU: NEC; Provided_By: SUBCO
C119-C124 C129 C131 C134-C136 C139-C143 = MCD-00006: Capacitor, MLCC, 100nF, 16V, X7R, 10%, 0402, T=0.5mm; Manufacturer_Part_Number: CC0402KRX7R7BB104; Manufacturer: YAGEO; Alternate_Manufacturer_Part_Number: GCM155R71C104KA55D; Alternate_Manufacturer: MURATA; Provided_By: SUBCO; ECCN_US: EAR99; ECCN_EU: NEC
C128 C130 C144 = MCD-01355: Capacitor, MLCC, 10uF, 4V, X5R, 20%, 0402, T=0,5mm; Manufacturer_Part_Number: GRM155R60G106ME44; Manufacturer: MURATA; ECCN_US: EAR99; ECCN_EU: NEC; Provided_By: Subcon; Initial_Board_Reference: MB1372
C145 C148 C149 = MCD-00010: Capacitor, MLCC, 1uF, 16V, X5R, 10%, 0603, T=0,8mm; Manufacturer_Part_Number: CC0603KRX5R7BB105; Manufacturer: YAGEO; Provided_By: Subcon; Initial_Board_Reference: MB1274
CN21 = MCD-00558: Battery Coin Cell holder, CR1220_12mm, Height 4.25mm; Part_Type: Connector; Manufacturer_Part_Number: S8411-45R; Manufacturer: HARWIN; Provided_By: Subcon; Initial_Board_Reference: MB1331
HW18 HW24-HW29 HW41 = MCD-00043: as HW7 on sheet MCU_IO
JP4 JP5 JP16 JP18 JP19 = MCD-00683: Header, 2x1, 2,54mm, VR, TH, Height 5.84mm/2.54mm - Shunt Fitted by default; Part_Type: Connector; Manufacturer_Part_Number: TSW-102-07-x-S; Manufacturer: SAMTEC; Provided_By: Subcon; Initial_Board_Reference: MB1331
JP17 JP23 JP24 = MCD-00684: as JP10 on sheet MCU_IO
L1 = MCD-01060: Inductor, 2.2uH, 20%, Isat 0.7A, DCR 0.156Ohm, 0805; Manufacturer: MURATA; Part_Preference: Recommended
SB76 = MCD-00071: as SB11 on sheet MCU_IO
TP5 TP6 TP11-TP13 TP23 = MCD-01506: Test Point trought hole 1mm/2mm; Part_Type: Mechanical; Initial_Board_Reference: MB1372; Item Type: Item; Path: ws/MCD_ApplicationBoards/Lists/MCDPARTSdatabase
TP10 = MCD-00074: Test Point 1mm; Part_Type: Mechanical; Initial_Board_Reference: MB1274; Path: ws/MCD_ApplicationBoards/Lists/MCDPARTSdatabase; Item Type: Item
U5 = MCD-01902: as U5 on sheet MCU_IO

## Sheet MOTOR_CONTROL.SchDoc: MOTOR CONTROL
size A4; Date: Not used; ApprovedBy: Not used; CheckedBy: Not used; Author: Not used; CompanyName: STMicroelectronics; DrawnBy: Not used; Engineer: Not used; Organization: Not used; Address1: Not used; Address2: Not used; Address3: Not used; Address4: Not used; DocumentNumber: 20; Revision: Not used; SheetNumber: 20; SheetTotal: 24
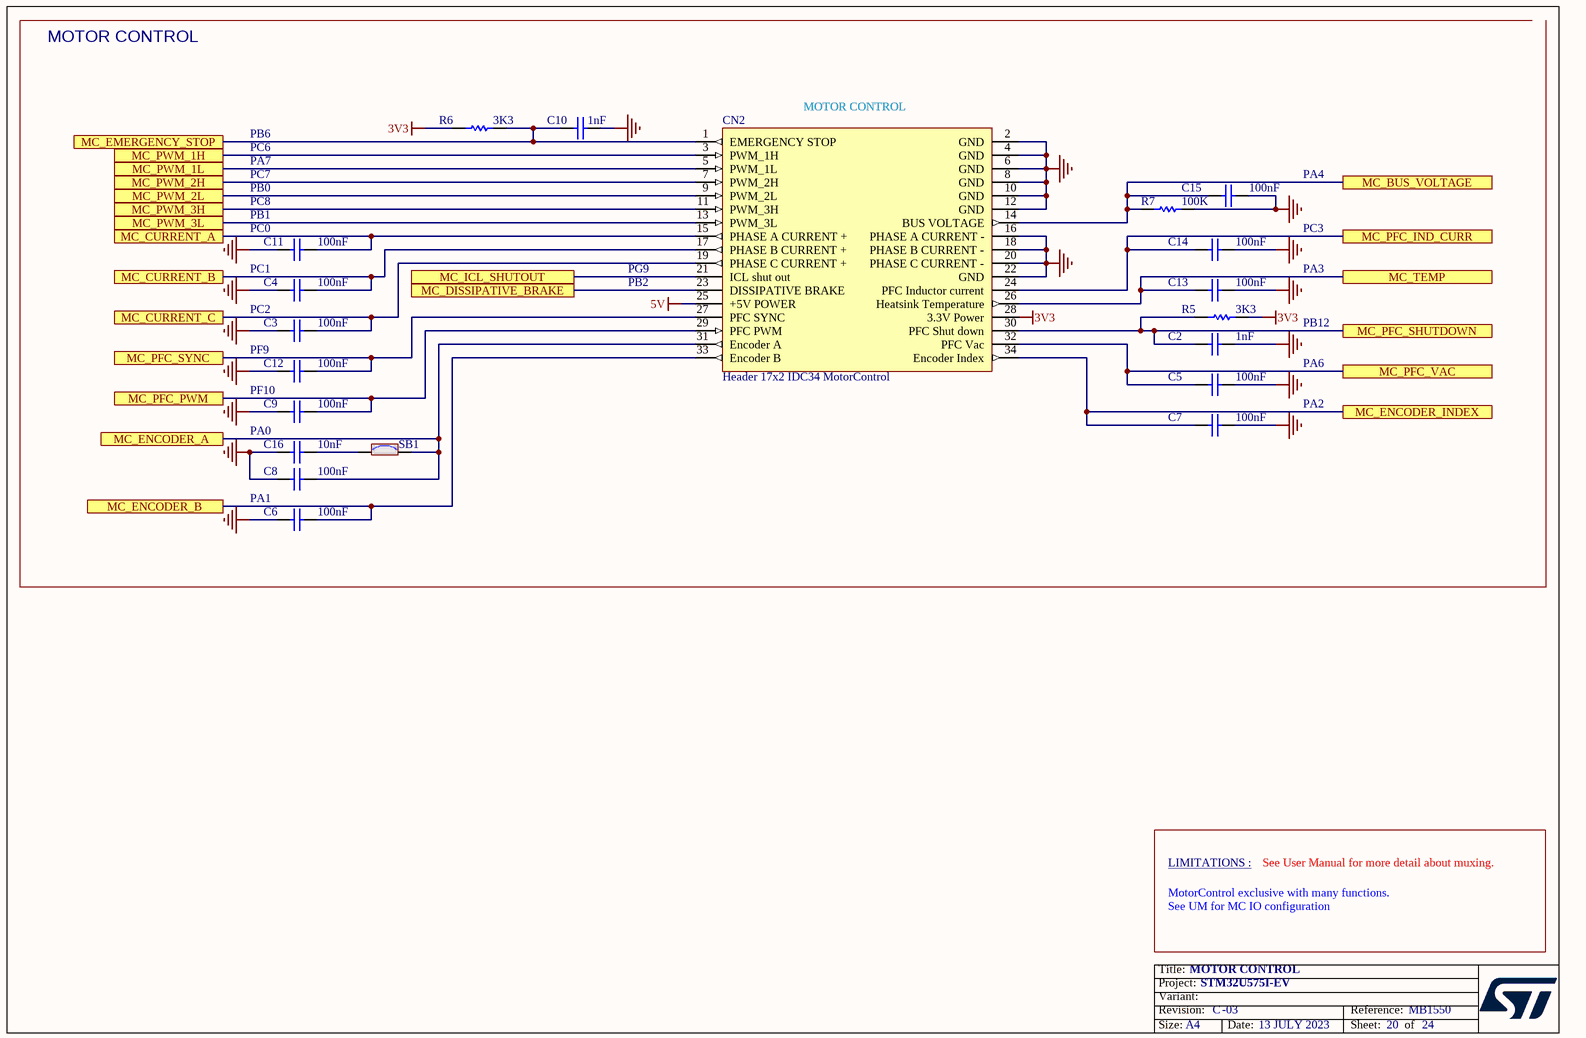
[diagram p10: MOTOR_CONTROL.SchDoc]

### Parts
C2  value 1nF  [C0402]
C3  value 100nF  [C0402]
C4  value 100nF  [C0402]
C5  value 100nF  [C0402]
C6  value 100nF  [C0402]
C7  value 100nF  [C0402]
C8  value 100nF  [C0402]
C9  value 100nF  [C0402]
C10  value 1nF  [C0402]
C11  value 100nF  [C0402]
C12  value 100nF  [C0402]
C13  value 100nF  [C0402]
C14  value 100nF  [C0402]
C15  value 100nF  [C0402]
C16  value 10nF  [C0402]
CN2  value Header 17x2 IDC34 MotorControl  [CON_SAMTEC_TST-117-01-T-D]
R5  value 3K3  [R0603]
R6  value 3K3  [R0603]
R7  value 100K  [R0603]
SB1  (no value)  [SOLDER-BRIDGE_R0603-0R]

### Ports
MC_BUS_VOLTAGE, MC_CURRENT_A, MC_CURRENT_B, MC_CURRENT_C, MC_DISSIPATIVE_BRAKE, MC_EMERGENCY_STOP, MC_ENCODER_A, MC_ENCODER_B, MC_ENCODER_INDEX, MC_ICL_SHUTOUT, MC_PFC_IND_CURR, MC_PFC_PWM, MC_PFC_SHUTDOWN, MC_PFC_SYNC, MC_PFC_VAC, MC_PWM_1H, MC_PWM_1L, MC_PWM_2H, MC_PWM_2L, MC_PWM_3H, MC_PWM_3L, MC_TEMP

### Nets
3V3: CN2.28(3.3V_Power) R5.2 R6.1
5V: CN2.25(+5V_POWER)
GND: C2.1 C3.1 C4.2 C5.1 C6.2 C7.1 C8.2 C9.2 C10.2 C11.2 C12.1 C13.1 C14.1 C15.1 C16.1 CN2.2(GND) CN2.4(GND) CN2.6(GND) CN2.8(GND) CN2.10(GND) CN2.12(GND) CN2.16(PHASE_A_CURRENT_-) CN2.18(PHASE_B_CURRENT_-) CN2.20(PHASE_C_CURRENT_-) CN2.22(GND) R7.1
MC_BUS_VOLTAGE: C15.2 CN2.14(BUS_VOLTAGE) R7.2 ; port MC_BUS_VOLTAGE
MC_CURRENT_A: C11.1 CN2.15(PHASE_A_CURRENT_+) ; port MC_CURRENT_A
MC_CURRENT_B: C4.1 CN2.17(PHASE_B_CURRENT_+) ; port MC_CURRENT_B
MC_CURRENT_C: C3.2 CN2.19(PHASE_C_CURRENT_+) ; port MC_CURRENT_C
MC_DISSIPATIVE_BRAKE: CN2.23(DISSIPATIVE_BRAKE) ; port MC_DISSIPATIVE_BRAKE
MC_EMERGENCY_STOP: C10.1 CN2.1(EMERGENCY_STOP) R6.2 ; port MC_EMERGENCY_STOP
MC_ENCODER_A: C8.1 CN2.31(Encoder_A) SB1.1 ; port MC_ENCODER_A
MC_ENCODER_B: C6.1 CN2.33(Encoder_B) ; port MC_ENCODER_B
MC_ENCODER_INDEX: C7.2 CN2.34(Encoder_Index) ; port MC_ENCODER_INDEX
MC_ICL_SHUTOUT: CN2.21(ICL_shut_out) ; port MC_ICL_SHUTOUT
MC_PFC_IND_CURR: C14.2 CN2.24(PFC_Inductor_current) ; port MC_PFC_IND_CURR
MC_PFC_PWM: C9.1 CN2.29(PFC_PWM) ; port MC_PFC_PWM
MC_PFC_SHUTDOWN: C2.2 CN2.30(PFC_Shut_down) R5.1 ; port MC_PFC_SHUTDOWN
MC_PFC_SYNC: C12.2 CN2.27(PFC_SYNC) ; port MC_PFC_SYNC
MC_PFC_VAC: C5.2 CN2.32(PFC_Vac) ; port MC_PFC_VAC
MC_PWM_1H: CN2.3(PWM_1H) ; port MC_PWM_1H
MC_PWM_1L: CN2.5(PWM_1L) ; port MC_PWM_1L
MC_PWM_2H: CN2.7(PWM_2H) ; port MC_PWM_2H
MC_PWM_2L: CN2.9(PWM_2L) ; port MC_PWM_2L
MC_PWM_3H: CN2.11(PWM_3H) ; port MC_PWM_3H
MC_PWM_3L: CN2.13(PWM_3L) ; port MC_PWM_3L
MC_TEMP: C13.2 CN2.26(Heatsink_Temperature) ; port MC_TEMP
NetC16_2: C16.2 SB1.2

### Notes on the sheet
- MOTOR CONTROL
- (near CN2) MOTOR CONTROL
- PC7
- PB6
- PC6
- PA7
- PA4
- (near C11) PC0
- PB0
- (near C11) PB1
- (near C11) PC8
- PC3
- PC1
- PC2
- PG9
- PB2
- PA3
- PF9
- PA6
- PB12
- PA0
- PF10
- PA2
- PA1
- LIMITATIONS :
- MotorControl exclusive with many functions.
  See UM for MC IO configuration
- See User Manual for more detail about muxing.

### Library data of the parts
C2 C10 = MCD-00198: Capacitor, MLCC, 1nF, 16V, X7R, 10%, 0402, T=0.5mm; Manufacturer_Part_Number: CC0402KRX7R7BB102; Manufacturer: YAGEO; Provided_By: Subcon
C3-C9 C11-C15 = MCD-00006: as C119-C124 on sheet MCU_PWR
C16 = MCD-00011: Capacitor, MLCC, 10nF, 16V, X7R, 10%, 0402, T=0.5mm; Manufacturer_Part_Number: CC0402KRX7R7BB103; Manufacturer: YAGEO; Provided_By: Subcon; Initial_Board_Reference: MB1274
CN2 = MCD-00583: Header, 17x2, 2.54mm, VR, TH, Height 8.89mm/2.92mm, shrouded; Manufacturer_Part_Number: TST-117-01-T-D; Manufacturer: SAMTEC; Part_Type: Connector; Alternate_Manufacturer_Part_Number: BHFS03-34G01BT1; Alternate_Manufacturer: WINPIN; Provided_By: Subcon; Initial_Board_Reference: MB1331
R5 R6 = MCD-00352: Resistor,3K3,0603,1%,1/10W; Manufacturer_Part_Number: RC0603FR-073K3L; Manufacturer: YAGEO; Provided_By: Subcon
R7 = MCD-00223: Resistor,100K,0603,1%,1/10W; Manufacturer_Part_Number: RC0603FR-07100KL; Manufacturer: YAGEO; Provided_By: Subcon; Initial_Board_Reference: MB1319
SB1 = MCD-00071: as SB11 on sheet MCU_IO

## Sheet OCTOSPI.SchDoc: OCTOSPI
size A4; Date: Not used; ApprovedBy: Not used; CheckedBy: Not used; Author: Not used; CompanyName: STMicroelectronics; DrawnBy: Not used; Engineer: Not used; Organization: Not used; Address1: Not used; Address2: Not used; Address3: Not used; Address4: Not used; DocumentNumber: 9; Revision: Not used; SheetNumber: 9; SheetTotal: 24
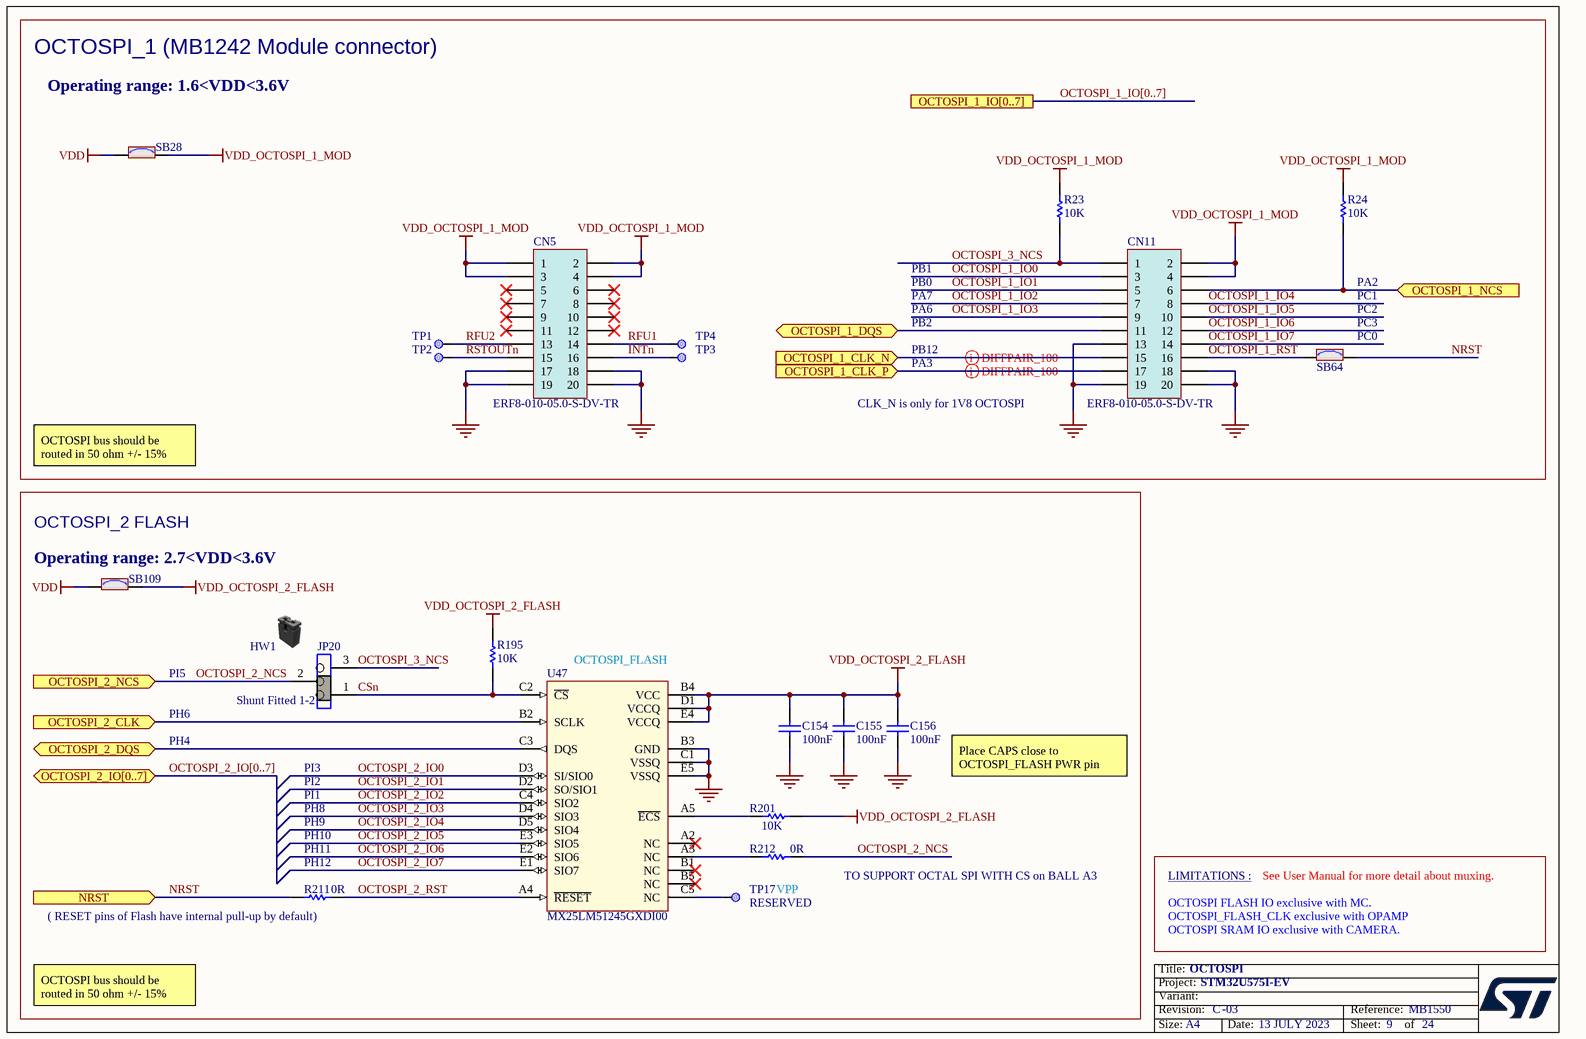
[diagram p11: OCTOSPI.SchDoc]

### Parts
C154  value 100nF  [C0402]
C155  value 100nF  [C0402]
C156  value 100nF  [C0402]
CN5  value ERF8-010-05.0-S-DV-TR  [CON_SAMTEC_ERF8-010-050-S-DV-TR]
CN11  value ERF8-010-05.0-S-DV-TR  [CON_SAMTEC_ERF8-010-050-S-DV-TR]
HW1  (no value)  (mechanical)
JP20  value Shunt Fitted 1-2  [CON_SAMTEC_TSW-103-07-F-S]
R23  value 10K  [R0603]
R24  value 10K  [R0603]
R195  value 10K  [R0603]
R201  value 10K  [R0603]
R211  value 0R  [R0603]
R212  value 0R  [R0603]
SB28  (no value)  [SOLDER-BRIDGE_R0603-0R]
SB64  SB_ON  [SOLDER-BRIDGE_R0603-0R]  (value not drawn)
SB109  (no value)  [SOLDER-BRIDGE_R0603-0R]
TP1  Test Point  [TP_SMD_1MM]  (value not drawn)  (no BOM)
TP2  Test Point  [TP_SMD_1MM]  (value not drawn)  (no BOM)
TP3  Test Point  [TP_SMD_1MM]  (value not drawn)  (no BOM)
TP4  Test Point  [TP_SMD_1MM]  (value not drawn)  (no BOM)
TP17  value VPP  [TP_SMD_1MM]  (no BOM)
U47  MX25LM51245GXDI00  [ICC_BGA24_5X5-BALL-ARRAY_6X8_P1]

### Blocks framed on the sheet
OCTOSPI_1 (MB1242 Module connector): CN5 CN11 R23 R24 SB28 SB64 TP1-TP4
OCTOSPI_2 FLASH: C154-C156 HW1 JP20 R195 R201 R211 R212 SB109 TP17 U47

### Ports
NRST (in), OCTOSPI_1_CLK_N (in), OCTOSPI_1_CLK_P (in), OCTOSPI_1_DQS (bidir), OCTOSPI_1_IO[0..7], OCTOSPI_1_NCS (in), OCTOSPI_2_CLK (in), OCTOSPI_2_DQS (bidir), OCTOSPI_2_IO[0..7] (bidir), OCTOSPI_2_NCS (in)

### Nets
GND: C154.1 C155.1 C156.1 CN5.17 CN5.18 CN5.19 CN5.20 CN11.13 CN11.18 CN11.19 CN11.20 U47.B3(GND) U47.C1(VSSQ) U47.E5(VSSQ)
VDD: SB28.1 SB109.1
VDD_OCTOSPI_1_MOD: CN5.1 CN5.2 CN5.3 CN5.4 CN11.2 CN11.4 R23.2 R24.2 SB28.2
VDD_OCTOSPI_2_FLASH: C154.2 C155.2 C156.2 R195.2 R201.1 SB109.2 U47.B4(VCC) U47.D1(VCCQ) U47.E4(VCCQ)
CSn: JP20.1 R195.1 U47.C2(~{CS})
INTn: CN5.16 TP3.1
NRST: R211.1 SB64.1 ; port NRST
OCTOSPI_1_CLK_N: CN11.15 ; port OCTOSPI_1_CLK_N
OCTOSPI_1_CLK_P: CN11.17 ; port OCTOSPI_1_CLK_P
OCTOSPI_1_DQS: CN11.11 ; port OCTOSPI_1_DQS
OCTOSPI_1_IO0: CN11.3
OCTOSPI_1_IO1: CN11.5
OCTOSPI_1_IO2: CN11.7
OCTOSPI_1_IO3: CN11.9
OCTOSPI_1_IO4: CN11.8
OCTOSPI_1_IO5: CN11.10
OCTOSPI_1_IO6: CN11.12
OCTOSPI_1_IO7: CN11.14
OCTOSPI_1_NCS: CN11.6 R24.1 ; port OCTOSPI_1_NCS
OCTOSPI_1_RST: CN11.16 SB64.2
OCTOSPI_2_CLK: U47.B2(SCLK) ; port OCTOSPI_2_CLK
OCTOSPI_2_DQS: U47.C3(DQS) ; port OCTOSPI_2_DQS
OCTOSPI_2_IO0: U47.D3(SI/SIO0)
OCTOSPI_2_IO1: U47.D2(SO/SIO1)
OCTOSPI_2_IO2: U47.C4(SIO2)
OCTOSPI_2_IO3: U47.D4(SIO3)
OCTOSPI_2_IO4: U47.D5(SIO4)
OCTOSPI_2_IO5: U47.E3(SIO5)
OCTOSPI_2_IO6: U47.E2(SIO6)
OCTOSPI_2_IO7: U47.E1(SIO7)
OCTOSPI_2_NCS: JP20.2 R212.2 ; port OCTOSPI_2_NCS
OCTOSPI_2_RST: R211.2 U47.A4(~{RESET})
OCTOSPI_3_NCS: CN11.1 JP20.3 R23.1
RFU1: CN5.14 TP4.1
RFU2: CN5.13 TP1.1
RSTOUTn: CN5.15 TP2.1
NetR201_2: R201.2 U47.A5(~{ECS})
NetR212_1: R212.1 U47.A3(NC)
NetTP17_1: TP17.1 U47.C5(NC)

Not connected (* = marked no-connect by the designer): CN5 5* 6* 7* 8* 9* 10* 11* 12*; U47 A2(NC)* B1(NC)* B5(NC)*

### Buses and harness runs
bus OCTOSPI_1_IO[0..7] = port OCTOSPI_1_IO[0..7]
bus OCTOSPI_2_IO[0..7] = port OCTOSPI_2_IO[0..7]

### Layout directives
differential pair: OCTOSPI_1_CLK_N, OCTOSPI_1_CLK_P

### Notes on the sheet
- Operating range: 1.6<VDD<3.6V
- PB1
- PA6
- PA7
- PB0
- (near SB64) PC2
- PC1
- PA2
- PA3
- PB2
- PB12
- (near SB64) PC3
- (near SB64) PC0
- CLK_N is only for 1V8 OCTOSPI
- OCTOSPI bus should be routed in 50 ohm +/- 15%
- (near SB109) Operating range: 2.7<VDD<3.6V
- PI5
- PH6
- (near U47) OCTOSPI_FLASH
- PH4
- PI3
- PI2
- Place CAPS close to OCTOSPI_FLASH PWR pin
- PI1
- PH8
- PH9
- PH10
- (near R211) PH11
- (near R211) ( RESET pins of Flash have internal pull-up by default)
- (near R211) PH12
- (near TP17) RESERVED
- TO SUPPORT OCTAL SPI WITH CS on BALL A3
- OCTOSPI_FLASH_CLK exclusive with OPAMP
- LIMITATIONS :
- OCTOSPI FLASH IO exclusive with MC.
- See User Manual for more detail about muxing.
- OCTOSPI SRAM IO exclusive with CAMERA.

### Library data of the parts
C154-C156 = MCD-00006: as C119-C124 on sheet MCU_PWR
CN5 CN11 = MCD-00675: Socket High Speed, 10x2, 0.8mm, Center Strip Contacts, VR, SMT, Height 5.33 mm; Part_Type: Connector; Manufacturer: SAMTEC; Provided_By: SUBCO; ECCN_US: EAR99; ECCN_EU: NEC
HW1 = MCD-00043: as HW7 on sheet MCU_IO
JP20 = MCD-00684: as JP10 on sheet MCU_IO
R23 R24 R195 R201 = MCD-00220: Resistor,10K,0603,1%,1/10W; Manufacturer_Part_Number: RC0603FR-0710KL; Manufacturer: YAGEO; Provided_By: Subcon; Initial_Board_Reference: MB1319
R211 R212 = MCD-00056: as R153 on sheet MCU_IO
SB28 SB109 = MCD-00071: as SB11 on sheet MCU_IO
SB64 = MCD-00071: Solder Bridge ON; Part_Type: Mechanical; Manufacturer_Part_Number: RC0603JR-070RL; Manufacturer: YAGEO; Provided_By: SUBCO
TP1-TP4 = MCD-00074: Test Point 1mm; Part_Type: Mechanical
TP17 = MCD-00074: as TP7 on sheet MCU_IO
U47 = MCD-00246: Memory,Octo-SPI-NOR,512Mb,2048x16,133MHz,3V,DTR,BGA24, CMOS MXSMIO; Part_Type: IC; Manufacturer: MACRONIX; ECCN_US: tbd; Provided_By: SUBCO

## Sheet PERIPHERAL.SchDoc: PERIPHERAL
size A4; Date: Not used; ApprovedBy: Not used; CheckedBy: Not used; Author: Not used; CompanyName: STMicroelectronics; DrawnBy: Not used; Engineer: Not used; Organization: Not used; Address1: Not used; Address2: Not used; Address3: Not used; Address4: Not used; DocumentNumber: 15; Revision: Not used; SheetNumber: 15; SheetTotal: 24
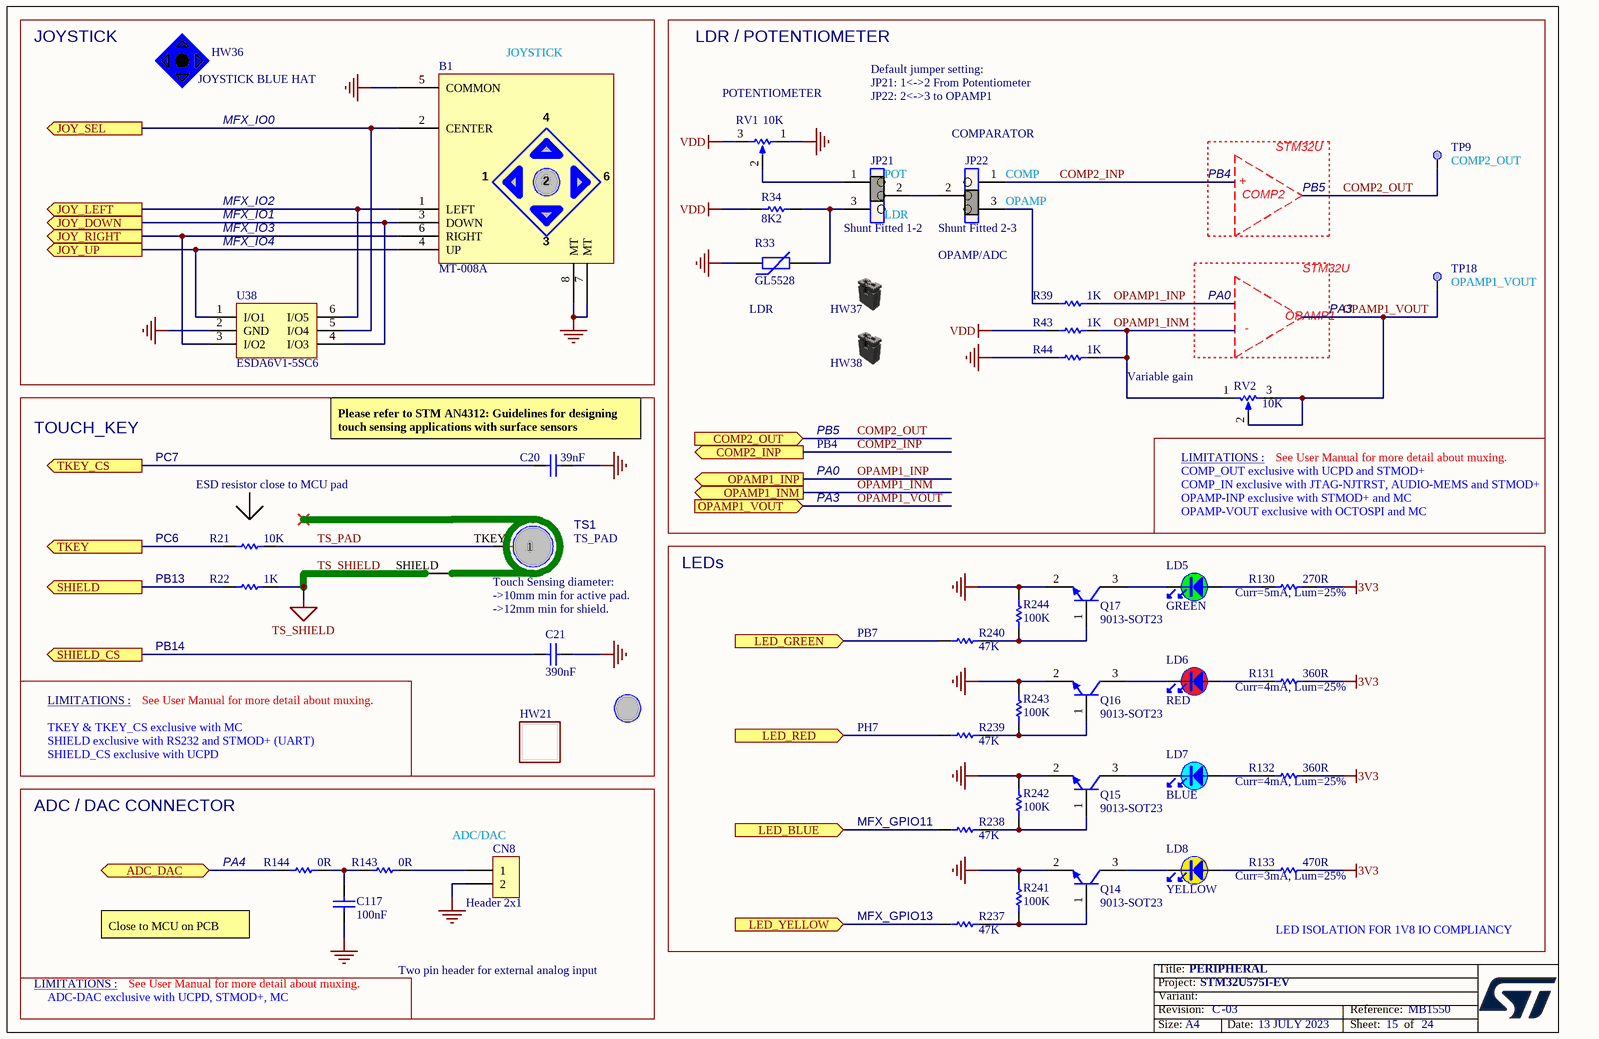
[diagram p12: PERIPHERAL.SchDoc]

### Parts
B1  value MT-008A  [SWI_XIEJIA_MT-008A_6P]
C20  value 39nF  [C1206_H0P85]
C21  value 390nF  [C0402]  (hidden comment: Capacitor)
C117  value 100nF  [C0603]
CN8  value Header 2x1  [CON_SAMTEC_TSW-102-07-G-S]
HW21  (no value)  (mechanical)
HW36  value JOYSTICK BLUE HAT  (mechanical)
HW37  (no value)  (mechanical)
HW38  (no value)  (mechanical)
JP21  value Shunt Fitted 1-2  [CON_SAMTEC_TSW-103-07-F-S]
JP22  value Shunt Fitted 2-3  [CON_SAMTEC_TSW-103-07-F-S]  (hidden comment: Jumper_Header 3x1 Fitted 2-3)
LD5  value GREEN  [LED_0603_OSRAM_LG-Q396-PS-35_GREEN_1A2K_H0P4]
LD6  value RED  [LED_0603_VISHAY_VLMS1300-GS08_RED_1A2K_H0P8]
LD7  value BLUE  [LED_0603_SMD-B_BLUE_H0P4]  (hidden comment: LED_blue)
LD8  value YELLOW  [LED_0603_OSRAM_LY-Q396-P1Q2-36_YELLOW_1A2K_H0P4]  (hidden comment: LED_yellow)
Q14  value 9013-SOT23  [NPN_SOT23]
Q15  value 9013-SOT23  [NPN_SOT23]
Q16  value 9013-SOT23  [NPN_SOT23]
Q17  value 9013-SOT23  [NPN_SOT23]
R21  value 10K  [R0603]
R22  value 1K  [R0603]
R33  value GL5528  [PHO_SENBAN_GL55XX]
R34  value 8K2  [R0603]
R39  value 1K  [R0603]
R43  value 1K  [R0603]
R44  value 1K  [R0603]
R130  value 270R  [R0603]
R131  value 360R  [R0603]
R132  value 360R  [R0603]
R133  value 470R  [R0603]  (hidden comment: Resistor)
R143  value 0R  [R0603]
R144  value 0R  [R0603]
R237  value 47K  [R0603]
R238  value 47K  [R0603]
R239  value 47K  [R0603]
R240  value 47K  [R0603]
R241  value 100K  [R0603]
R242  value 100K  [R0603]
R243  value 100K  [R0603]
R244  value 100K  [R0603]
RV1  value 10K  [POT_BOURNS_3386P-1-101TLF]  (hidden comment: POTENTIOMETER)
RV2  value 10K  [POT_BOURNS_3314J-1]
TP9  value COMP2_OUT  [TP_SMD_1MM]  (no BOM)
TP18  value OPAMP1_VOUT  [TP_SMD_1MM]  (no BOM)
TS1  value TS_PAD  [TSB_TOUCH-SENSING-BUTTON_TS-PAD-10_SHIELD-14]  (no BOM)
U38  value ESDA6V1-5SC6  [ESD_SOT23-6L]

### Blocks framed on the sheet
JOYSTICK: B1 HW36 U38
LDR / POTENTIOMETER: HW37 HW38 JP21 JP22 R33 R34 R39 R43 R44 RV1 RV2 TP9 TP18
TOUCH_KEY: C20 C21 HW21 R21 R22 TS1
LEDs: LD5-LD8 Q14-Q17 R130-R133 R237-R244
ADC / DAC CONNECTOR: C117 CN8 R143 R144

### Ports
ADC_DAC (bidir), COMP2_INP (out), COMP2_OUT (in), JOY_DOWN (out), JOY_LEFT (out), JOY_RIGHT (out), JOY_SEL (out), JOY_UP (out), LED_BLUE (in), LED_GREEN (in), LED_RED (in), LED_YELLOW (in), OPAMP1_INM (out), OPAMP1_INP (out), OPAMP1_VOUT (in), SHIELD (out), SHIELD_CS (out), TKEY (out), TKEY_CS (out)

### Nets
3V3: R130.2 R131.2 R132.2 R133.2
GND: B1.5(COMMON) B1.7(MT) B1.8(MT) C20.2 C21.2 C117.1 CN8.2 Q14.2(E) Q15.2(E) Q16.2(E) Q17.2(E) R33.1 R44.1 R241.1 R242.1 R243.1 R244.1 RV1.1(BOT) U38.2(GND)
TS_SHIELD: R22.2 TS1.SHIELD
VDD: R34.1 R43.1 RV1.3(TOP)
ADC_DAC: R144.2 ; port ADC_DAC
COMP2_INP: JP22.1 ; port COMP2_INP
COMP2_OUT: TP9.1 ; port COMP2_OUT
JOY_DOWN: B1.3(DOWN) U38.4(I/O3) ; port JOY_DOWN
JOY_LEFT: B1.1(LEFT) U38.6(I/O5) ; port JOY_LEFT
JOY_RIGHT: B1.6(RIGHT) U38.3(I/O2) ; port JOY_RIGHT
JOY_SEL: B1.2(CENTER) U38.5(I/O4) ; port JOY_SEL
JOY_UP: B1.4(UP) U38.1(I/O1) ; port JOY_UP
LED_BLUE: R238.1 ; port LED_BLUE
LED_YELLOW: R237.1 ; port LED_YELLOW
OPAMP1_INM: R43.2 R44.2 RV2.1(BOT) ; port OPAMP1_INM
OPAMP1_INP: R39.2 ; port OPAMP1_INP
OPAMP1_VOUT: RV2.2(TAP) RV2.3(TOP) TP18.1 ; port OPAMP1_VOUT
PB7: R240.1 ; port LED_GREEN
PH7: R239.1 ; port LED_RED
SHIELD: R22.1 ; port SHIELD
SHIELD_CS: C21.1 ; port SHIELD_CS
TKEY: R21.1 ; port TKEY
TKEY_CS: C20.1 ; port TKEY_CS
TS_PAD: R21.2 TS1.TKEY(1)
NetC117_2: C117.2 R143.1 R144.1
NetCN8_1: CN8.1 R143.2
NetJP21_1: JP21.1 RV1.2(TAP)
NetJP21_2: JP21.2 JP22.2
NetJP21_3: JP21.3 R33.2 R34.2
NetJP22_3: JP22.3 R39.1
NetLD5_1: LD5.1 R130.1
NetLD5_2: LD5.2 Q17.3(C)
NetLD6_1: LD6.1 R131.1
NetLD6_2: LD6.2 Q16.3(C)
NetLD7_1: LD7.1 R132.1
NetLD7_2: LD7.2 Q15.3(C)
NetLD8_1: LD8.1 R133.1
NetLD8_2: LD8.2 Q14.3(C)
NetQ14_1: Q14.1(B) R237.2 R241.2
NetQ15_1: Q15.1(B) R238.2 R242.2
NetQ16_1: Q16.1(B) R239.2 R243.2
NetQ17_1: Q17.1(B) R240.2 R244.2

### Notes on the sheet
- (near B1) JOYSTICK
- (near RV1) POTENTIOMETER
- Default jumper setting:
  JP21: 1<->2 From Potentiometer
  JP22: 2<->3 to OPAMP1
- MFX_IO0
- (near JP21) POT
- (near JP22) COMPARATOR
- (near JP22) COMP
- PB4
- STM32U
- MFX_IO2
- MFX_IO1
- MFX_IO3
- MFX_IO4
- (near JP21) LDR
- (near JP22) OPAMP
- +
- COMP2
- PB5
- (near R33) LDR
- (near JP22) OPAMP/ADC
- PA0
- PA3
- Variable gain
- -
- OPAMP1
- (near C20) Please refer to STM AN4312: Guidelines for designing touch sensing applications with surface sensors
- PC7
- ESD resistor close to MCU pad
- (near RV2) LIMITATIONS :
- COMP_IN exclusive with JTAG-NJTRST, AUDIO-MEMS and STMOD+
- COMP_OUT exclusive with UCPD and STMOD+
- OPAMP-INP exclusive with STMOD+ and MC
- OPAMP-VOUT exclusive with OCTOSPI and MC
- (near RV2) See User Manual for more detail about muxing.
- PB13
- PC6
- PB14
- (near TS1) Touch Sensing diameter:
  ->10mm min for active pad.
  ->12mm min for shield.
- PB7
- (near R130) Curr=5mA, Lum=25%
- LIMITATIONS :
- See User Manual for more detail about muxing.
- (near R131) Curr=4mA, Lum=25%
- SHIELD exclusive with RS232 and STMOD+ (UART)
- TKEY & TKEY_CS exclusive with MC
- SHIELD_CS exclusive with UCPD
- PH7
- (near R132) Curr=4mA, Lum=25%
- (near CN8) ADC/DAC
- (near R238) MFX_GPIO11
- (near R144) PA4
- (near R237) MFX_GPIO13
- (near R133) Curr=3mA, Lum=25%
- Close to MCU on PCB
- Two pin header for external analog input
- LED ISOLATION FOR 1V8 IO COMPLIANCY
- ADC-DAC exclusive with UCPD, STMOD+, MC

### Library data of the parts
B1 = MCD-00132: Joystick, 4 dir, 1 OK; Part_Type: Misc; Manufacturer: XIEJIA Electronics; Provided_By: Subcon; Initial_Board_Reference: MB1262
C20 = MCD-01939: Capacitor, COG, 39nF,50V, 5%, 1206, T=0.85mm; Manufacturer_Part_Number: GRM3195C1H393JA01D; Manufacturer: MURATA; ECCN_US: EAR99; ECCN_EU: NEC; Provided_By: SUBCO
C21 = MCD-02154: Capacitor, MLCC, 390nF, 10V, X5R, 10%, 0402, T=0,5mm; Manufacturer_Part_Number: GMD155R61A394KE11J; Manufacturer: MURATA; Alternate_Manufacturer_Part_Number: N\A; ECCN_US: EAR99; ECCN_EU: NEC; Provided_By: SUBCO
C117 = MCD-00211: Capacitor, MLCC, 100nF, 16V, X7R, 10%, 0603, T=0,8mm; Manufacturer_Part_Number: CC0603KRX7R7BB104; Manufacturer: YAGEO; Provided_By: Subcon; Initial_Board_Reference: MB1319
CN8 = MCD-00032: Header, 2x1, 2,54mm, VR, TH, Height 5.84mm/2.54mm; Part_Type: Connector; Manufacturer_Part_Number: TSW-102-07-x-S; Manufacturer: SAMTEC; Provided_By: Subcon; Initial_Board_Reference: MB1274
HW21 = MCD-01201: Plastic protection for Sensitive Touch Key: square 14mmx14mmx1mm; Part_Type: Misc; Value: tbd; Provided_By: SUBCO
HW36 = MCD-01337: Joystick BLue Hat; Part_Type: Mechanical; Manufacturer_Part_Number: KTSC-62-B; Manufacturer: JIUBABA; Provided_By: Subcon; Initial_Board_Reference: MB1372; Remark: mechanical part only no footprint
HW37 HW38 = MCD-00043: as HW7 on sheet MCU_IO
JP21 = MCD-00684: as JP10 on sheet MCU_IO
JP22 = MCD-00685: Header, 3x1, 2,54mm, VR, TH, Height 5.84mm/2.54mm - Shunt Fitted 2-3 by default; Part_Type: Connector; Manufacturer_Part_Number: TSW-103-07-F-S; Manufacturer: SAMTEC; Provided_By: SUBCO; Initial_Board_Reference: MB1331; Path: ws/MCD_ApplicationBoards/Lists/MCDPARTSdatabase; Item Type: Item
LD5 = MCD-00588: LED Green, 0603 SMD, Forward Voltage Typ=2V, Max=2.5V; Part_Type: Display; Manufacturer_Part_Number: LG Q396-PS-35; Manufacturer: OSRAM OPTO SEMICONDUCTORS; Alternate_Manufacturer_Part_Number: VLMTG1300-GS08; Alternate_Manufacturer: VISHAY SEMICONDUCTOR OPTO DIVISION; Provided_By: Subcon; Initial_Board_Reference: MB1331
LD6 = MCD-00587: LED Red, 0603 SMD, 2V Forward Voltage; Part_Type: Display; Manufacturer_Part_Number: VLMS1300-GS08; Manufacturer: VISHAY; Alternate_Manufacturer_Part_Number: LS Q976-NR-1; Alternate_Manufacturer: OSRAM OPTO SEMICONDUCTORS; Provided_By: Subcon; Initial_Board_Reference: MB1331
LD7 = MCD-02786: LED, Blue, VF: Min=2.5V, Max=3.1V, 10mA, 0603; Part_Type: Display; Part_Preference: Recommended; Manufacturer: EVERLIGHT; Manufacturer_Part_Number: 19-217/BHC-ZL1M2RY/6T; Full_Alternate_Internal_Part_Number: MCD-01131; Component_Country_Of_Origin: China; ShowFields: YES; ID: 4898
LD8 = MCD-01061: LED Yellow, 0603 SMD, Forward Voltage min=1.7V, Typ=2V, Max=2.3V; Part_Type: Display; Manufacturer_Part_Number: LY Q396-P1Q2-36; Manufacturer: OSRAM OPTO SEMICONDUCTORS; Provided_By: SUBCO
Q14-Q17 = MCD-00073: NPN Bipolar Transistor; Part_Type: IC; Manufacturer_Part_Number: BSR14; Manufacturer: NXP; ECCN_US: EAR99; ECCN_EU: NEC; Provided_By: Subcon; Initial_Board_Reference: MB1274
R21 = MCD-00220: as R23 on sheet OCTOSPI
R22 R39 R43 R44 = MCD-00070: Resistor,1K,0603,1%,1/10W; Manufacturer_Part_Number: RC0603FR-071KL; Manufacturer: YAGEO; Provided_By: Subcon; Initial_Board_Reference: MB1274
R33 = MCD-01158: GL55 series  photoconductive cell; Part_Type: Misc; Manufacturer: SHENZHEN SENBAN OPTICAL & ELECTRONIC CO. LTD; ECCN_US: NA; Provided_By: Subcon; Initial_Board_Reference: MB1397
R34 = MCD-00530: Resistor,8K2,0603,1%,1/10W; Manufacturer_Part_Number: RC0603FR-078K2L; Manufacturer: YAGEO; Provided_By: Subcon
R130 = MCD-00442: Resistor,270R,0603,1%,1/10W; Manufacturer_Part_Number: RC0603FR-07270RL; Manufacturer: YAGEO; Provided_By: Subcon
R131 R132 = MCD-00462: Resistor,360R,0603,1%,1/10W; Manufacturer_Part_Number: RC0603FR-07360RL; Manufacturer: YAGEO; Provided_By: Subcon
R133 = MCD-00354: Resistor,470R,0603,1%,1/10W; Manufacturer_Part_Number: RC0603FR-07470RL; Manufacturer: YAGEO; BMS_Part_Number: 9129906; ECCN_US: EAR99; ECCN_EU: NEC; Provided_By: SUBCO
R143 R144 = MCD-00056: as R153 on sheet MCU_IO
R237-R240 = MCD-00222: Resistor,47K,0603,1%,1/10W; Manufacturer_Part_Number: RC0603FR-0747KL; Manufacturer: YAGEO; Provided_By: Subcon; Initial_Board_Reference: MB1319
R241-R244 = MCD-00223: as R7 on sheet MOTOR_CONTROL
RV1 = MCD-02051: Trimmer, 10K, 3386, +/-10%, 1/2W, T=4.83mm; Part_Type: Resistor; Part_Preference: Recommended; Manufacturer: BOURNS; Manufacturer_Part_Number: 3386P-1-103TLF; Order_Code_RS: 167-5241
RV2 = MCD-01169: 4mm Square Trimming Potentiometer 10K OHM 0.25W PC PIN; Part_Type: Resistor; Manufacturer_Part_Number: 3314J-1-103; Manufacturer: BOURNS; Provided_By: Subcon; Initial_Board_Reference: MB1397
TP9 TP18 = MCD-00074: as TP7 on sheet MCU_IO
TS1 = MCD-01194: -Touch Sensing button: diameter 10mm min,  active shield diameter 12mm min; Part_Type: Misc; Manufacturer_Part_Number: Touch_sensing_Button; Provided_By: Subcon; Initial_Board_Reference: MB1372
U38 = MCD-01066: 5 unidirectional Transil diodes ESD protection; Part_Type: Diode; Manufacturer: STMICROELECTRONICS; Provided_By: Subcon; Initial_Board_Reference: MB1331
